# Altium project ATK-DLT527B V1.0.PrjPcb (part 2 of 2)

## Sheet 09_ATK_T527_AUDIO.SchDoc
size A4; Author: ALIENTEK; Revision: 0; Version: V1.0; SheetSize: A4
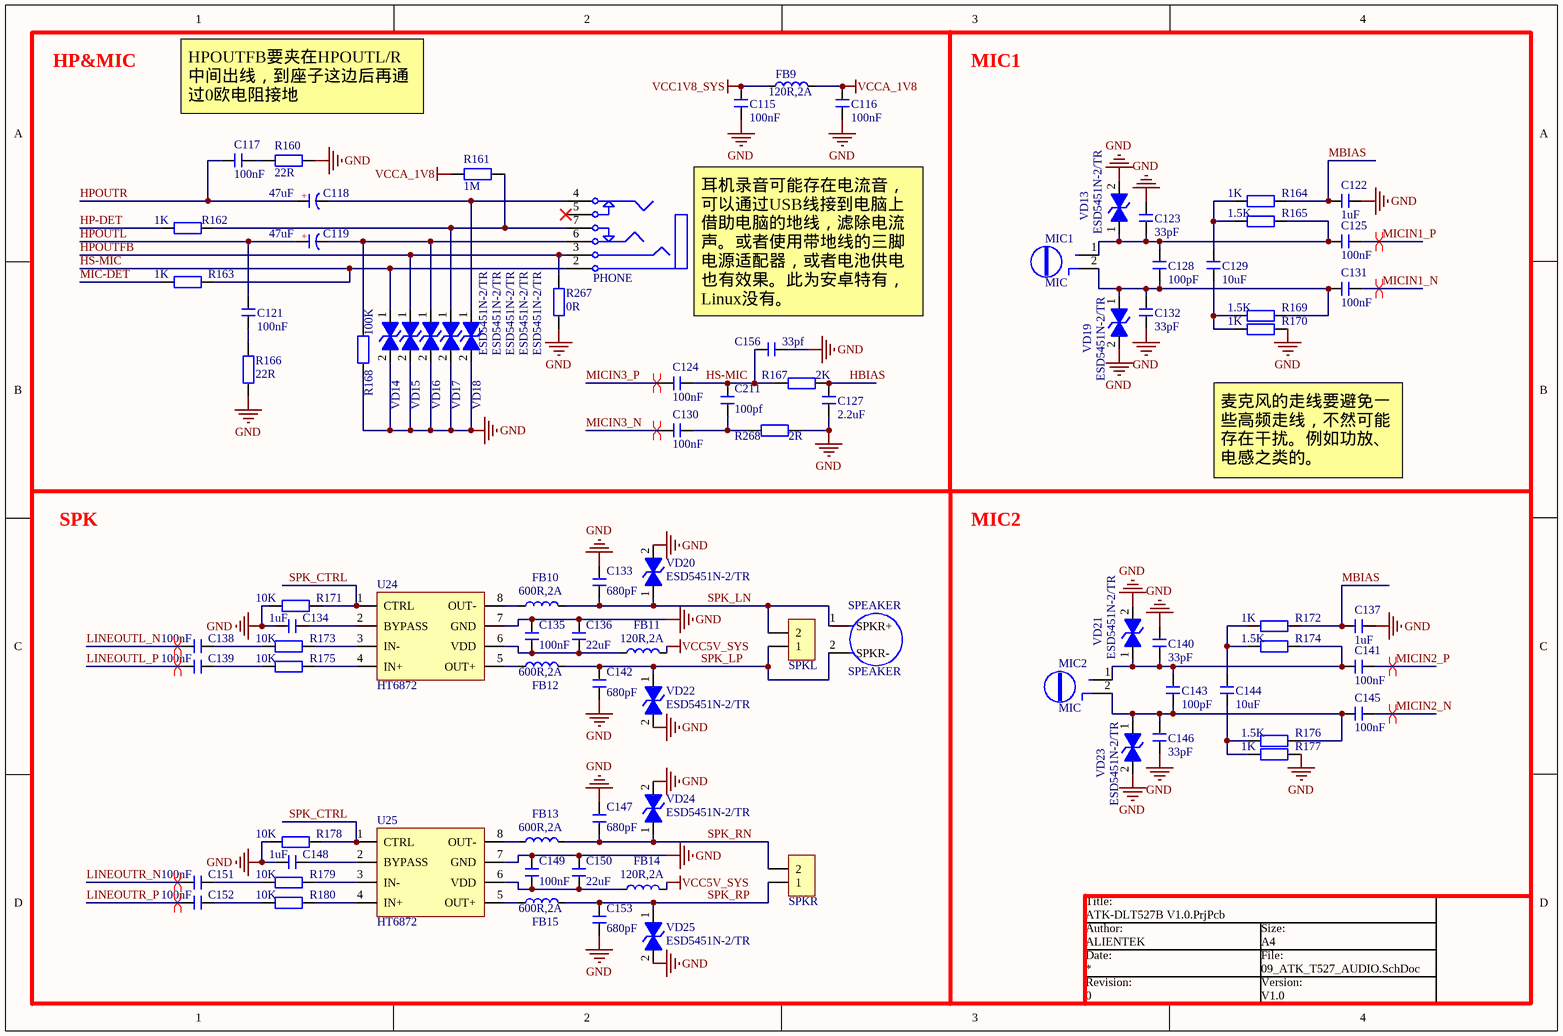
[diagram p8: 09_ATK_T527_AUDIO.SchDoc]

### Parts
C115  100nF  [C 0402]
C116  100nF  [C 0402]
C117  100nF  [C 0402]
C118  47uF  [CM B(4*5.4)]
C119  47uF  [CM B(4*5.4)]
C121  100nF  [C 0402]
C122  1uF  [C 0402]
C123  33pF  [C 0402]
C124  100nF  [C 0402]
C125  100nF  [C 0402]
C127  2.2uF  [C 0402]
C128  100pF  [C 0402]
C129  10uF  [C 0603]
C130  100nF  [C 0402]
C131  100nF  [C 0402]
C132  33pF  [C 0402]
C133  680pF  [C 0402]
C134  1uF  [C 0402]
C135  100nF  [C 0402]
C136  22uF  [C 0603]
C137  1uF  [C 0402]
C138  100nF  [C 0402]
C139  100nF  [C 0402]
C140  33pF  [C 0402]
C141  100nF  [C 0402]
C142  680pF  [C 0402]
C143  100pF  [C 0402]
C144  10uF  [C 0603]
C145  100nF  [C 0402]
C146  33pF  [C 0402]
C147  680pF  [C 0402]
C148  1uF  [C 0402]
C149  100nF  [C 0402]
C150  22uF  [C 0603]
C151  100nF  [C 0402]
C152  100nF  [C 0402]
C153  680pF  [C 0402]
C156  33pf  [C 0402]
C211  100pf  [C 0402]
FB9  120R,2A  [L 0603]
FB10  600R,2A  [L 0603]
FB11  120R,2A  [L 0603]
FB12  600R,2A  [L 0603]
FB13  600R,2A  [L 0603]
FB14  120R,2A  [L 0603]
FB15  600R,2A  [L 0603]
MIC1  MIC  [MIC-6022]
MIC2  MIC  [MIC-6022]
PHONE  PJ342  [PJ342A]  (value not drawn)
R160  22R  [R 0402]
R161  1M  [R 0402]
R162  1K  [R 0402]
R163  1K  [R 0402]
R164  1K  [R 0402]
R165  1.5K  [R 0402]
R166  22R  [R 0402]
R167  2K  [R 0402]
R168  100K  [R 0402]
R169  1.5K  [R 0402]
R170  1K  [R 0402]
R171  10K  [R 0402]
R172  1K  [R 0402]
R173  10K  [R 0402]
R174  1.5K  [R 0402]
R175  10K  [R 0402]
R176  1.5K  [R 0402]
R177  1K  [R 0402]
R178  10K  [R 0402]
R179  10K  [R 0402]
R180  10K  [R 0402]
R267  0R  [R 0402]
R268  2R  [R 0402]
SPEAKER  SPEAKER  [SPEAKER]
SPKL  Header 1X2  [XH2.54-2P H-T]  (value not drawn)
SPKR  Header 1X2  [XH2.54-2P H-T]  (value not drawn)
U24  HT6872  [SOP8_N]
U25  HT6872  [SOP8_N]
VD13  ESD5451N-2/TR  [ESD0402]
VD14  ESD5451N-2/TR  [ESD0402]
VD15  ESD5451N-2/TR  [ESD0402]
VD16  ESD5451N-2/TR  [ESD0402]
VD17  ESD5451N-2/TR  [ESD0402]
VD18  ESD5451N-2/TR  [ESD0402]
VD19  ESD5451N-2/TR  [ESD0402]
VD20  ESD5451N-2/TR  [ESD0402]
VD21  ESD5451N-2/TR  [ESD0402]
VD22  ESD5451N-2/TR  [ESD0402]
VD23  ESD5451N-2/TR  [ESD0402]
VD24  ESD5451N-2/TR  [ESD0402]
VD25  ESD5451N-2/TR  [ESD0402]

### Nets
GND: C115.2 C116.2 C122.1 C123.1 C127.1 C132.2 C133.1 C134.2 C135.1 C136.1 C137.1 C140.1 C142.2 C146.2 C147.1 C148.2 C149.1 C150.1 C153.2 C156.2 R160.2 R166.2 R168.1 R170.1 R171.2 R177.1 R178.2 R267.2 R268.1 U24.7(GND) U25.7(GND) VD13.2 VD14.2 VD15.2 VD16.2 VD17.2 VD18.2 VD19.2 VD20.2 VD21.2 VD22.2 VD23.2 VD24.2 VD25.2
VCC1V8_SYS: C115.1 FB9.1
VCC5V_SYS: FB11.2 FB14.2
VCCA_1V8: C116.1 FB9.2 R161.2
HBIAS: C127.2 R167.1
HP-DET: R162.1
HPOUTFB: PHONE.3 R267.1 VD15.1
HPOUTL: C119.1(A) C121.2
HPOUTR: C117.2 C118.1(A)
HS-MIC: C124.1 C156.1 C211.2 PHONE.2 R163.1 R167.2 VD14.1
LINEOUTL_N: C138.2
LINEOUTL_P: C139.2
LINEOUTR_N: C151.2
LINEOUTR_P: C152.2
MBIAS: C122.2 C137.2 R164.1 R172.1
MIC-DET: R163.2
MICIN1_N: C131.1
MICIN1_P: C125.1
MICIN2_N: C145.1
MICIN2_P: C141.1
MICIN3_N: C130.2
MICIN3_P: C124.2
SPK_CTRL: R171.1 R178.1 U24.1(CTRL) U25.1(CTRL)  [project net PI10]
SPK_LN: C133.2 FB10.2 SPEAKER.1(SPKR+) SPKL.2 VD20.1
SPK_LP: C142.1 FB12.2 SPEAKER.2(SPKR-) SPKL.1 VD22.1
SPK_RN: C147.2 FB13.2 SPKR.2 VD24.1
SPK_RP: C153.1 FB15.2 SPKR.1 VD25.1
NetC117_1: C117.1 R160.1
NetC118_2: C118.2(K) PHONE.4 VD18.1
NetC119_2: C119.2(K) PHONE.6 R168.2 VD16.1
NetC121_1: C121.1 R166.1
NetC123_2: C123.2 C125.2 C128.1 MIC1.1(VCC) R165.1 VD13.1
NetC128_2: C128.2 C131.2 C132.1 MIC1.2(GND) R169.1 VD19.1
NetC129_1: C129.1 R164.2 R165.2
NetC129_2: C129.2 R169.2 R170.2
NetC130_1: C130.1 C211.1 R268.2
NetC134_1: C134.1 U24.2(BYPASS)
NetC135_2: C135.2 C136.2 FB11.1 U24.6(VDD)
NetC138_1: C138.1 R173.2
NetC139_1: C139.1 R175.2
NetC140_2: C140.2 C141.2 C143.1 MIC2.1(VCC) R174.1 VD21.1
NetC143_2: C143.2 C145.2 C146.1 MIC2.2(GND) R176.1 VD23.1
NetC144_1: C144.1 R172.2 R174.2
NetC144_2: C144.2 R176.2 R177.2
NetC148_1: C148.1 U25.2(BYPASS)
NetC149_2: C149.2 C150.2 FB14.1 U25.6(VDD)
NetC151_1: C151.1 R179.2
NetC152_1: C152.1 R180.2
NetFB10_1: FB10.1 U24.8(OUT-)
NetFB12_1: FB12.1 U24.5(OUT+)
NetFB13_1: FB13.1 U25.8(OUT-)
NetFB15_1: FB15.1 U25.5(OUT+)
NetPHONE_7: PHONE.7 R161.1 R162.2 VD17.1
NetR173_1: R173.1 U24.3(IN-)
NetR175_1: R175.1 U24.4(IN+)
NetR179_1: R179.1 U25.3(IN-)
NetR180_1: R180.1 U25.4(IN+)

Not connected (* = marked no-connect by the designer): PHONE 5*

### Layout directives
differential pair: LINEOUTL_N, LINEOUTL_P, LINEOUTR_N, LINEOUTR_P, MICIN1_N, MICIN1_P, MICIN2_N, MICIN2_P, MICIN3_N, MICIN3_P

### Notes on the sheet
- HP&MIC
- HPOUTFB要夹在HPOUTL/R中间出线，到座子这边后再通过0欧电阻接地
- MIC1
- (near C156) 耳机录音可能存在电流音，可以通过USB线接到电脑上借助电脑的地线，滤除电流声。或者使用带地线的三脚电源适配器，或者电池供电也有效果。此为安卓特有，Linux没有。
- 麦克风的走线要避免一些高频走线，不然可能存在干扰。例如功放、电感之类的。
- SPK
- MIC2

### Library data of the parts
C115-C117 C121-C125 C127-C153 C156 C211 = C: 无极性电容; BOM名称: 无极性贴片电容; 版权归属: 正点原子
C118 C119 = C-CM: 贴片电解电容; 版权归属: 源创客
FB9-FB15 = FB: 贴片磁珠; BOM名称: 小功率贴片电感; 版权归属: 正点原子; Parameter: 电感/磁珠
PHONE = Phone-PJ3583: 3.5耳机插座,带检测和麦克风; BOM名称: 耳机插座; 版权归属: 正点原子; Parameter: 接口器件
R160-R180 R267 R268 = R: 电阻; BOM名称: 贴片电阻; 版权归属: 正点原子
SPEAKER = SPEAKER: 喇叭2307
SPKL SPKR = Header 2: 2P接插件; 版权归属: 正点原子; Parameter: 接插件
U24 U25 = HT6872: 功放-4.7W单声道D类功放
VD13-VD25 = ESD5341N: ESD二极管-单向

## Sheet 10_ATK_T527_MIPICSI.SchDoc
size A4; Author: ALIENTEK; Revision: 0; Version: V1.0; SheetSize: A4
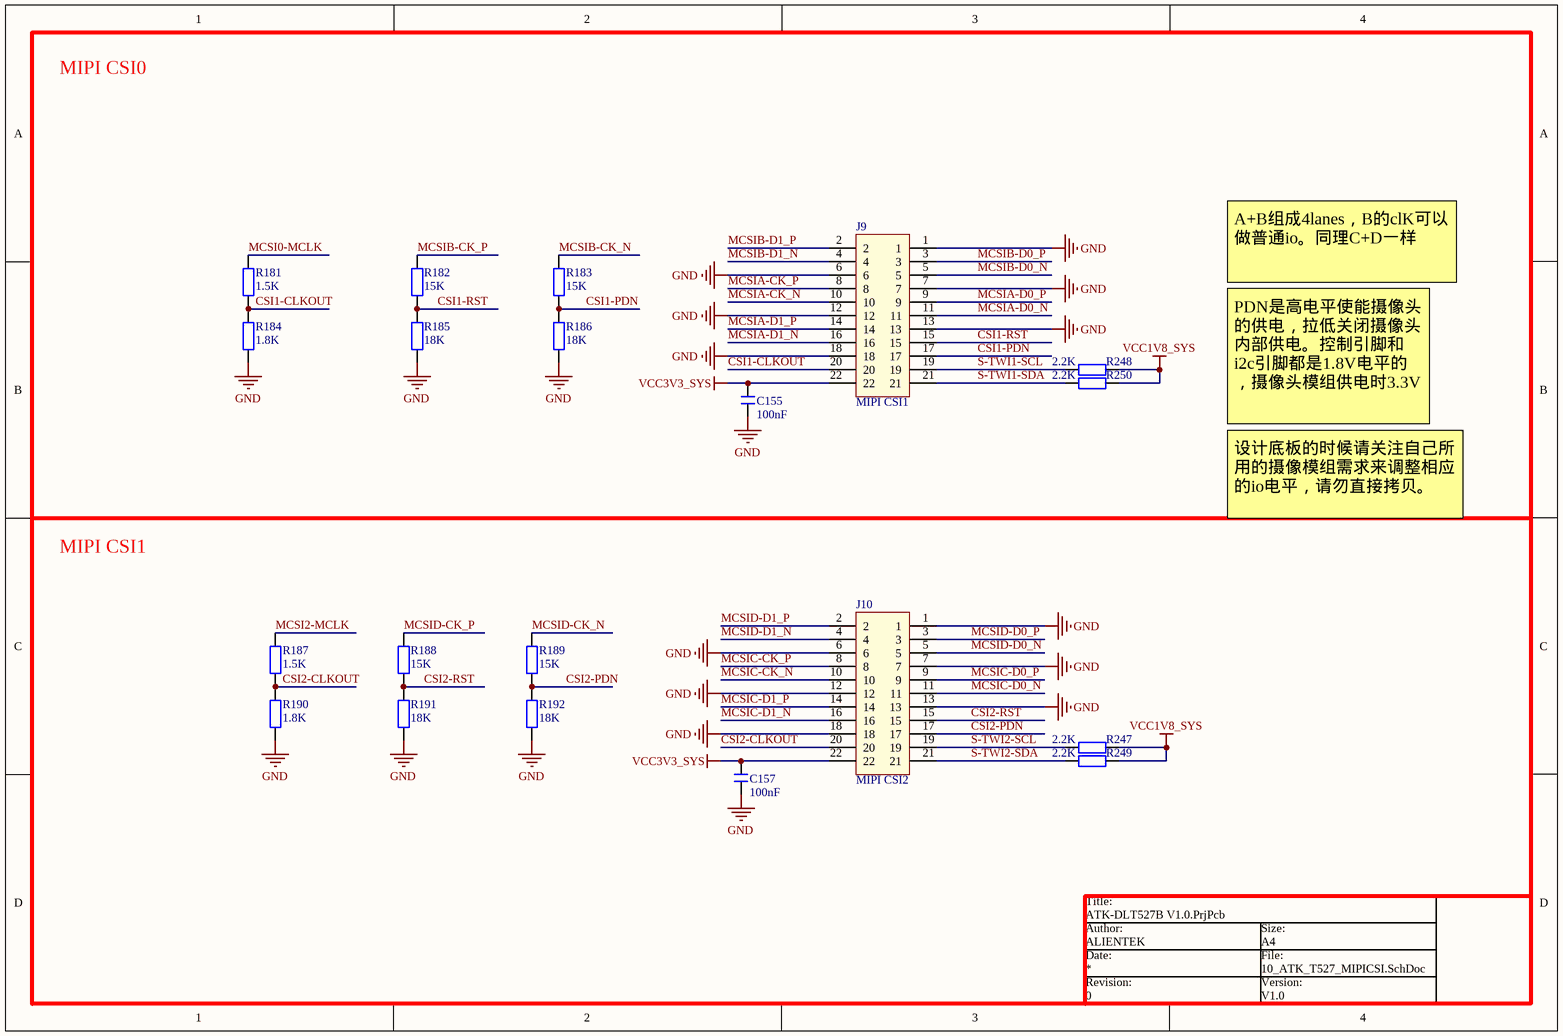
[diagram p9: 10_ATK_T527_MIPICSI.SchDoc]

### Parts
C155  100nF  [C 0402]
C157  100nF  [C 0402]
J9  MIPI CSI1  [HEADER 2.0 2X11P]
J10  MIPI CSI2  [HEADER 2.0 2X11P]
R181  1.5K  [R 0402]
R182  15K  [R 0402]
R183  15K  [R 0402]
R184  1.8K  [R 0402]
R185  18K  [R 0402]
R186  18K  [R 0402]
R187  1.5K  [R 0402]
R188  15K  [R 0402]
R189  15K  [R 0402]
R190  1.8K  [R 0402]
R191  18K  [R 0402]
R192  18K  [R 0402]
R247  2.2K  [R 0402]
R248  2.2K  [R 0402]
R249  2.2K  [R 0402]
R250  2.2K  [R 0402]

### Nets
GND: C155.1 C157.1 J9.1 J9.6 J9.7 J9.12 J9.13 J9.18 J10.1 J10.6 J10.7 J10.12 J10.13 J10.18 R184.1 R185.1 R186.1 R190.1 R191.1 R192.1
VCC1V8_SYS: R247.1 R248.1 R249.1 R250.1
VCC3V3_SYS: C155.2 C157.2 J9.22 J10.22
CSI1-CLKOUT: J9.20 R181.1 R184.2
CSI1-PDN: J9.17 R183.1 R186.2
CSI1-RST: J9.15 R182.1 R185.2
CSI2-CLKOUT: J10.20 R187.1 R190.2
CSI2-PDN: J10.17 R189.1 R192.2
CSI2-RST: J10.15 R188.1 R191.2
MCSI0-MCLK: R181.2
MCSI2-MCLK: R187.2
MCSIA-CK_N: J9.10
MCSIA-CK_P: J9.8
MCSIA-D0_N: J9.11
MCSIA-D0_P: J9.9
MCSIA-D1_N: J9.16
MCSIA-D1_P: J9.14
MCSIB-CK_N: R183.2
MCSIB-CK_P: R182.2
MCSIB-D0_N: J9.5
MCSIB-D0_P: J9.3
MCSIB-D1_N: J9.4
MCSIB-D1_P: J9.2
MCSIC-CK_N: J10.10
MCSIC-CK_P: J10.8
MCSIC-D0_N: J10.11
MCSIC-D0_P: J10.9
MCSIC-D1_N: J10.16
MCSIC-D1_P: J10.14
MCSID-CK_N: R189.2
MCSID-CK_P: R188.2
MCSID-D0_N: J10.5
MCSID-D0_P: J10.3
MCSID-D1_N: J10.4
MCSID-D1_P: J10.2
S-TWI1-SCL: J9.19 R248.2  [project net PM2]
S-TWI1-SDA: J9.21 R250.2  [project net PM3]
S-TWI2-SCL: J10.19 R247.2  [project net PM4]
S-TWI2-SDA: J10.21 R249.2  [project net PM5]

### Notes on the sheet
- MIPI CSI0
- A+B组成4lanes，B的clK可以做普通io。同理C+D一样
- PDN是高电平使能摄像头的供电，拉低关闭摄像头内部供电。控制引脚和i2c引脚都是1.8V电平的，摄像头模组供电时3.3V
- 设计底板的时候请关注自己所用的摄像模组需求来调整相应的io电平，请勿直接拷贝。
- MIPI CSI1

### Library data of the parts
C155 C157 = C: 无极性电容; BOM名称: 无极性贴片电容; 版权归属: 正点原子
J9 J10 = HEADER 2X11P
R181-R192 R247-R250 = R: 电阻; BOM名称: 贴片电阻; 版权归属: 正点原子

## Sheet 11_ATK_T527_CAN485.SchDoc
size A4; Author: ALIENTEK; Revision: 0; Version: V1.0; SheetSize: A4
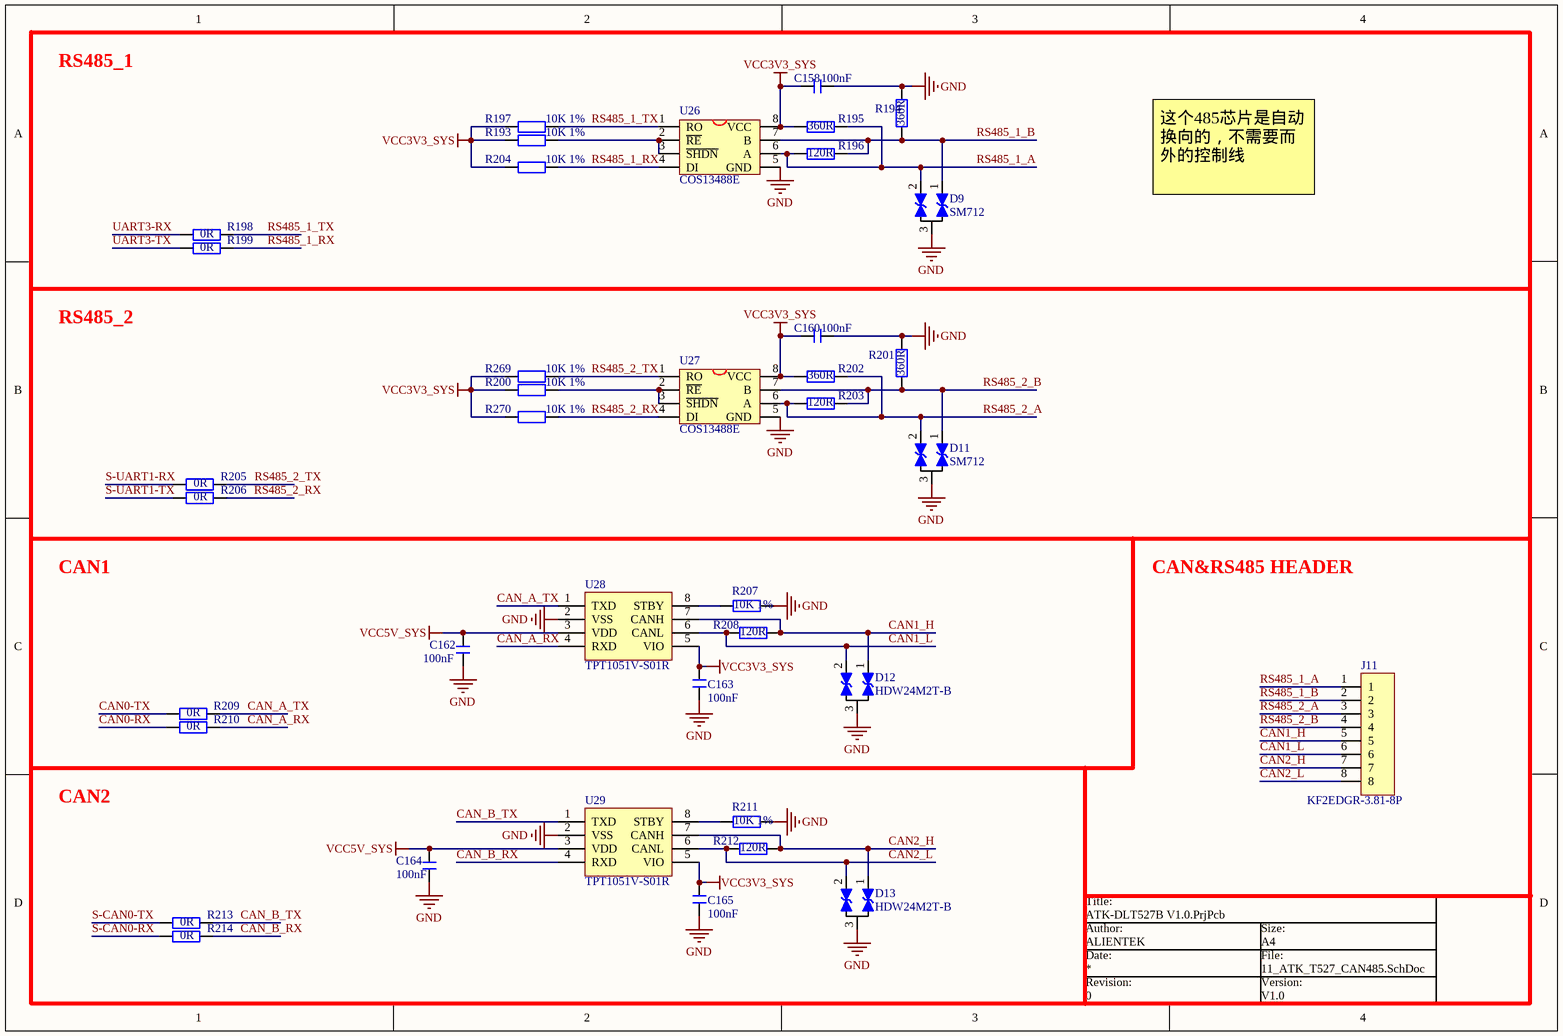
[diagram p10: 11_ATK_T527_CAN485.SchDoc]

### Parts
C158  100nF  [C 0402]
C160  100nF  [C 0402]
C162  100nF  [C 0402]
C163  100nF  [C 0402]
C164  100nF  [C 0402]
C165  100nF  [C 0402]
D9  SM712  [SOT23-3L]
D11  SM712  [SOT23-3L]
D12  HDW24M2T-B  [SOT23-3L]
D13  HDW24M2T-B  [SOT23-3L]
J11  KF2EDGR-3.81-8P  [KF2EDGR_3.81_8P]
R193  10K 1%  [R 0402]
R194  360R  [R 0402]
R195  360R  [R 0402]
R196  120R  [R 0402]
R197  10K 1%  [R 0402]
R198  0R  [R 0402]
R199  0R  [R 0402]
R200  10K 1%  [R 0402]
R201  360R  [R 0402]
R202  360R  [R 0402]
R203  120R  [R 0402]
R204  10K 1%  [R 0402]
R205  0R  [R 0402]
R206  0R  [R 0402]
R207  10K 1%  [R 0402]
R208  120R  [R 0402]
R209  0R  [R 0402]
R210  0R  [R 0402]
R211  10K 1%  [R 0402]
R212  120R  [R 0402]
R213  0R  [R 0402]
R214  0R  [R 0402]
R269  10K 1%  [R 0402]
R270  10K 1%  [R 0402]
U26  COS13488E  [SOP8_N]
U27  COS13488E  [SOP8_N]
U28  TPT1051V-S01R  [SOP8_N]
U29  TPT1051V-S01R  [SOP8_N]

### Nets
GND: C158.2 C160.2 C162.1 C163.2 C164.1 C165.2 D9.3 D11.3 D12.3 D13.3 R194.1 R201.1 R207.2 R211.2 U26.5(GND) U27.5(GND) U28.2(VSS) U29.2(VSS)
VCC3V3_SYS: C158.1 C160.1 C163.1 C165.1 R193.2 R195.2 R197.2 R200.2 R202.2 R204.2 R269.2 R270.2 U26.8(VCC) U27.8(VCC) U28.5(VIO) U29.5(VIO)
VCC5V_SYS: C162.2 C164.2 U28.3(VDD) U29.3(VDD)
CAN0-RX: R210.1
CAN0-TX: R209.1
CAN1_H: D12.1 J11.5 R208.1 U28.7(CANH)
CAN1_L: D12.2 J11.6 R208.2 U28.6(CANL)
CAN2_H: D13.1 J11.7 R212.1 U29.7(CANH)
CAN2_L: D13.2 J11.8 R212.2 U29.6(CANL)
CAN_A_RX: R210.2 U28.4(RXD)
CAN_A_TX: R209.2 U28.1(TXD)
CAN_B_RX: R214.2 U29.4(RXD)
CAN_B_TX: R213.2 U29.1(TXD)
RS485_1_A: D9.2 J11.1 R195.1 R196.2 U26.6(A)
RS485_1_B: D9.1 J11.2 R194.2 R196.1 U26.7(B)
RS485_1_RX: R199.2 R204.1 U26.4(DI)
RS485_1_TX: R197.1 R198.2 U26.1(RO)
RS485_2_A: D11.2 J11.3 R202.1 R203.2 U27.6(A)
RS485_2_B: D11.1 J11.4 R201.2 R203.1 U27.7(B)
RS485_2_RX: R206.2 R270.1 U27.4(DI)
RS485_2_TX: R205.2 R269.1 U27.1(RO)
S-CAN0-RX: R214.1  [project net PL5]
S-CAN0-TX: R213.1  [project net PL4]
S-UART1-RX: R205.1  [project net PL3]
S-UART1-TX: R206.1  [project net PL2]
UART3-RX: R198.1  [project net PI12]
UART3-TX: R199.1  [project net PI11]
NetR193_1: R193.1 U26.2(~{RE}) U26.3(~{SHDN})
NetR200_1: R200.1 U27.2(~{RE}) U27.3(~{SHDN})
NetR207_1: R207.1 U28.8(STBY)
NetR211_1: R211.1 U29.8(STBY)

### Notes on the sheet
- RS485_1
- 这个485芯片是自动换向的，不需要而外的控制线
- RS485_2
- CAN1
- CAN&RS485 HEADER
- CAN2

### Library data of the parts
C158 C160 C162-C165 = C: 无极性贴片电容; 版权归属: 正点原子
D9 D11-D13 = PESD2CAN: ESD
J11 = KF2EDGR-3.81-8P: 接线端子,8脚,间距3.81mm
R193-R197 R200-R204 R207 R208 R211 R212 R269 R270 = R: 贴片电阻; 版权归属: 正点原子
R198 R199 R205 R206 R209 R210 R213 R214 = R: 电阻; BOM名称: 贴片电阻; 版权归属: 正点原子
U28 U29 = MCP2562FDT

## Sheet 12_ATK_T527_DEVICE1.SchDoc
size A3; Date: 13; Author: ALIENTEK; Version: V1.0; SheetSize: A3
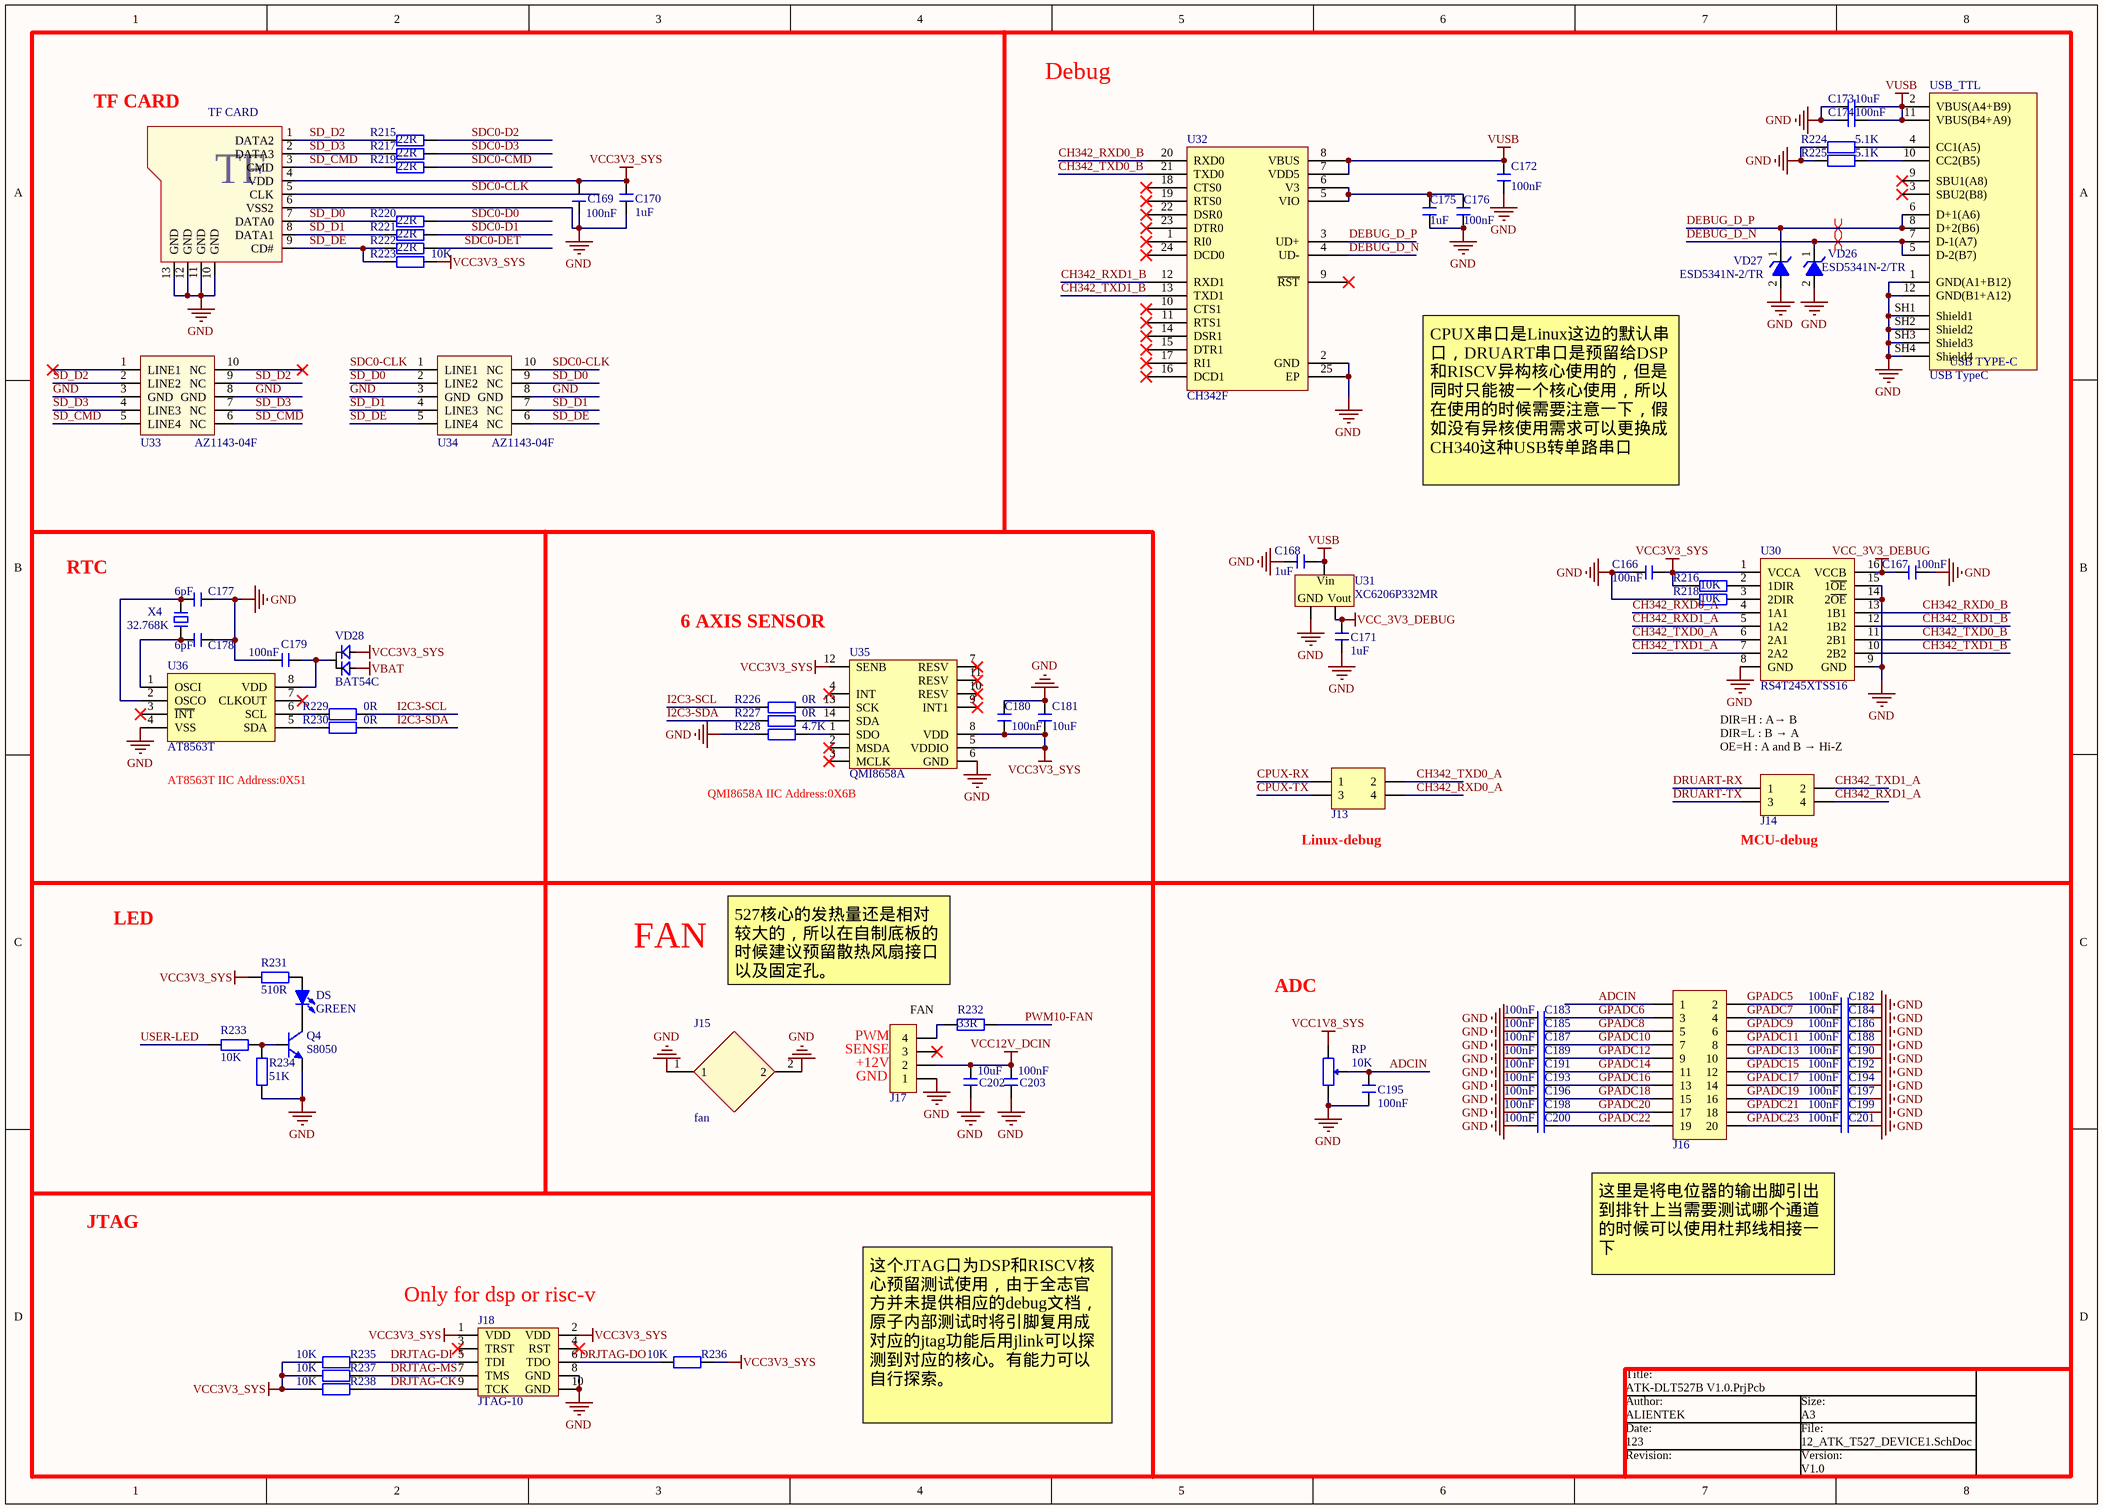
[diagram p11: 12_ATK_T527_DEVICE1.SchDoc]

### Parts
C166  100nF  [C 0402]
C167  100nF  [C 0402]
C168  1uF  [C 0402]
C169  100nF  [C 0402]
C170  1uF  [C 0402]
C171  1uF  [C 0402]
C172  100nF  [C 0402]
C173  10uF  [C 0603]
C174  100nF  [C 0402]
C175  1uF  [C 0402]
C176  100nF  [C 0402]
C177  6pF  [C 0402]
C178  6pF  [C 0402]
C179  100nF  [C 0402]
C180  100nF  [C 0402]
C181  10uF  [C 0603]
C182  100nF  [C 0402]
C183  100nF  [C 0402]
C184  100nF  [C 0402]
C185  100nF  [C 0402]
C186  100nF  [C 0402]
C187  100nF  [C 0402]
C188  100nF  [C 0402]
C189  100nF  [C 0402]
C190  100nF  [C 0402]
C191  100nF  [C 0402]
C192  100nF  [C 0402]
C193  100nF  [C 0402]
C194  100nF  [C 0402]
C195  100nF  [C 0402]
C196  100nF  [C 0402]
C197  100nF  [C 0402]
C198  100nF  [C 0402]
C199  100nF  [C 0402]
C200  100nF  [C 0402]
C201  100nF  [C 0402]
C202  10uF  [C 0603]
C203  100nF  [C 0402]
DS  GREEN  [LED 0805G]
J13  Header2X2  [Header 2.54 2X2P]  (value not drawn)
J14  Header2X2  [Header 2.54 2X2P]  (value not drawn)
J15  fan  [40X40MM_FAN_59MM]
J16  Header 2X10  [Header 2.54 2X10P]  (value not drawn)
J17  Header 1X4  [PH2.0-4P V-T]  (value not drawn)
J18  JTAG-10  [JTAG-10 2.0]
Q4  S8050  [SOT23-3N]
R215  22R  [R 0402]
R216  10K  [R 0402]
R217  22R  [R 0402]
R218  10K  [R 0402]
R219  22R  [R 0402]
R220  22R  [R 0402]
R221  22R  [R 0402]
R222  22R  [R 0402]
R223  10K  [R 0402]
R224  5.1K  [R 0402]
R225  5.1K  [R 0402]
R226  0R  [R 0402]
R227  0R  [R 0402]
R228  4.7K  [R 0402]
R229  0R  [R 0402]
R230  0R  [R 0402]
R231  510R  [R 0402]
R232  33R  [R 0402]
R233  10K  [R 0402]
R234  51K  [R 0402]
R235  10K  [R 0402]
R236  10K  [R 0402]
R237  10K  [R 0402]
R238  10K  [R 0402]
RP  10K  [3362P]
TF_CARD  SD-MICRO-TF  [SD-MICRO-TF]  (value not drawn)
U30  RS4T245XTSS16  [TSSOP16_N]
U31  XC6206P332MR  [SOT23-3L]
U32  CH342F  [VQFN-24_L4.0-W4.0-P0.50-TL-EP2.4]
U33  AZ1143-04F  [DFN2510P10E]
U34  AZ1143-04F  [DFN2510P10E]
U35  QMI8658A  [QFN14]
U36  AT8563T  [SOP8_N]
USB_TTL  USB TypeC  [USB2.0 Type-C]
VD26  ESD5341N-2/TR  [ESD0402]
VD27  ESD5341N-2/TR  [ESD0402]
VD28  BAT54C  [SOT23-3N]
X4  32.768K  [XTAL-2X6H]

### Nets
GND: C166.2 C167.1 C168.1 C169.1 C170.1 C171.1 C172.1 C173.1 C174.1 C175.1 C176.1 C177.1 C178.1 C179.1 C180.1 C181.2 C182.1 C183.1 C184.1 C185.1 C186.1 C187.1 C188.1 C189.1 C190.1 C191.1 C192.1 C193.1 C194.1 C195.2 C196.1 C197.1 C198.1 C199.1 C200.1 C201.1 C202.1 C203.1 J15.1 J15.2 J17.1 J18.8(GND) J18.10(GND) Q4.2(E) R218.1 R224.1 R225.1 R228.2 R234.1 RP.3 TF_CARD.6(VSS2) TF_CARD.10(GND) TF_CARD.11(GND) TF_CARD.12(GND) TF_CARD.13(GND) U30.8(GND) U30.9(GND) U30.14(2~{OE}) U30.15(1~{OE}) U31.1(GND) U32.2(GND) U32.25(EP) U33.3(GND) U33.8(GND) U34.3(GND) U34.8(GND) U35.6(GND) U36.4(VSS) USB_TTL.1(GND(A1+B12)) USB_TTL.12(GND(B1+A12)) USB_TTL.SH1(Shield1) USB_TTL.SH2(Shield2) USB_TTL.SH3(Shield3) USB_TTL.SH4(Shield4) VD26.2 VD27.2
VBAT: VD28.1
VCC1V8_SYS: RP.1
VCC3V3_SYS: C166.1 C169.2 C170.2 C180.2 C181.1 J18.1(VDD) J18.2(VDD) R216.2 R223.2 R231.1 R235.1 R236.2 R237.1 R238.1 TF_CARD.4(VDD) U30.1(VCCA) U35.5(VDDIO) U35.8(VDD) U35.12(SENB) VD28.2
VCC12V_DCIN: C202.2 C203.2 J17.2
VCC_3V3_DEBUG: C167.2 C171.2 U30.16(VCCB) U31.2(Vout)
VUSB: C168.2 C172.2 C173.2 C174.2 U31.3(Vin) U32.7(VDD5) U32.8(VBUS) USB_TTL.2(VBUS(A4+B9)) USB_TTL.11(VBUS(B4+A9))
ADCIN: C195.1 J16.1 RP.2
CH342_RXD0_A: J13.4 U30.4(1A1)
CH342_RXD0_B: U30.13(1B1) U32.20(RXD0)
CH342_RXD1_A: J14.4 U30.5(1A2)
CH342_RXD1_B: U30.12(1B2) U32.12(RXD1)
CH342_TXD0_A: J13.2 U30.6(2A1)
CH342_TXD0_B: U30.11(2B1) U32.21(TXD0)
CH342_TXD1_A: J14.2 U30.7(2A2)
CH342_TXD1_B: U30.10(2B2) U32.13(TXD1)
CPUX-RX: J13.1
CPUX-TX: J13.3
DEBUG_D_N: U32.4(UD-) USB_TTL.5(D-2(B7)) USB_TTL.7(D-1(A7)) VD26.1
DEBUG_D_P: U32.3(UD+) USB_TTL.6(D+1(A6)) USB_TTL.8(D+2(B6)) VD27.1
DRJTAG-CK: J18.9(TCK) R238.2
DRJTAG-DI: J18.5(TDI) R235.2
DRJTAG-DO: J18.6(TDO) R236.1
DRJTAG-MS: J18.7(TMS) R237.2
DRUART-RX: J14.1
DRUART-TX: J14.3
GPADC5: C182.2 J16.2
GPADC6: C183.2 J16.3
GPADC7: C184.2 J16.4
GPADC8: C185.2 J16.5
GPADC9: C186.2 J16.6
GPADC10: C187.2 J16.7
GPADC11: C188.2 J16.8
GPADC12: C189.2 J16.9
GPADC13: C190.2 J16.10
GPADC14: C191.2 J16.11
GPADC15: C192.2 J16.12
GPADC16: C193.2 J16.13
GPADC17: C194.2 J16.14
GPADC18: C196.2 J16.15
GPADC19: C197.2 J16.16
GPADC20: C198.2 J16.17
GPADC21: C199.2 J16.18
GPADC22: C200.2 J16.19
GPADC23: C201.2 J16.20
I2C3-SCL: R226.2 R229.2
I2C3-SDA: R227.2 R230.2
PWM10-FAN: R232.1  [project net PB6]
SD_CMD: R219.1 TF_CARD.3(CMD) U33.5(LINE4) U33.6(NC)
SD_D0: R220.1 TF_CARD.7(DATA0) U34.2(LINE2) U34.9(NC)
SD_D1: R221.1 TF_CARD.8(DATA1) U34.4(LINE3) U34.7(NC)
SD_D2: R215.1 TF_CARD.1(DATA2) U33.2(LINE2) U33.9(NC)
SD_D3: R217.1 TF_CARD.2(DATA3) U33.4(LINE3) U33.7(NC)
SD_DE: R222.1 R223.1 TF_CARD.9(CD#) U34.5(LINE4) U34.6(NC)
SDC0-CLK: TF_CARD.5(CLK) U34.1(LINE1) U34.10(NC)  [project net PF2]
SDC0-CMD: R219.2  [project net PF3]
SDC0-D0: R220.2  [project net PF1]
SDC0-D1: R221.2  [project net PF0]
SDC0-D2: R215.2  [project net PF5]
SDC0-D3: R217.2  [project net PF4]
SDC0-DET: R222.2  [project net PF6]
USER-LED: R233.1  [project net LVDS3-D0_P]
NetC175_2: C175.2 C176.2 U32.5(VIO) U32.6(V3)
NetC177_2: C177.2 U36.2(OSCO) X4.2
NetC178_2: C178.2 U36.1(OSCI) X4.1
NetC179_2: C179.2 U36.8(VDD) VD28.3
NetDS_1: DS.1(A) R231.2
NetDS_2: DS.2(K) Q4.3(C)
NetJ17_4: J17.4 R232.2
NetQ4_1: Q4.1(B) R233.2 R234.2
NetR216_1: R216.1 U30.2(1DIR)
NetR218_2: R218.2 U30.3(2DIR)
NetR224_2: R224.2 USB_TTL.4(CC1(A5))
NetR225_2: R225.2 USB_TTL.10(CC2(B5))
NetR226_1: R226.1 U35.13(SCK)
NetR227_1: R227.1 U35.14(SDA)
NetR228_1: R228.1 U35.1(SDO)
NetR229_1: R229.1 U36.6(SCL)
NetR230_1: R230.1 U36.5(SDA)

Not connected (* = marked no-connect by the designer): J17 3*; J18 3(TRST)* 4(RST)*; U32 1(RI0)* 9(~{RST})* 10(CTS1)* 11(RTS1)* 14(DSR1)* 15(DTR1)* 16(DCD1)* 17(RI1)* 18(CTS0)* 19(RTS0)* 22(DSR0)* 23(DTR0)* 24(DCD0)*; U33 1(LINE1)* 10(NC)*; U35 2(MSDA)* 3(MCLK)* 4(INT)* 7(RESV)* 9(INT1)* 10(RESV)* 11(RESV)*; U36 3(~{INT})* 7(CLKOUT)*; USB_TTL 3(SBU2(B8))* 9(SBU1(A8))*

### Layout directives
differential pair: DEBUG_D_N, DEBUG_D_P

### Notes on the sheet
- (near TF_CARD) TF CARD
- Debug
- CPUX串口是Linux这边的默认串口，DRUART串口是预留给DSP和RISCV异构核心使用的，但是同时只能被一个核心使用，所以在使用的时候需要注意一下，假如没有异核使用需求可以更换成CH340这种USB转单路串口
- RTC
- 6 AXIS SENSOR
- DIR=H : A→ B
- AT8563T IIC Address:0X51
- DIR=L : B → A
- (near J14) OE=H : A and B → Hi-Z
- (near U35) QMI8658A IIC Address:0X6B
- (near J13) Linux-debug
- (near J14) MCU-debug
- LED
- FAN
- 527核心的发热量还是相对较大的，所以在自制底板的时候建议预留散热风扇接口以及固定孔。
- ADC
- (near J17) SENSE
- (near J17) PWM
- (near J17) FAN
- (near J17) GND
- (near J17) +12V
- JTAG
- (near J18) Only for dsp or risc-v
- 这里是将电位器的输出脚引出到排针上当需要测试哪个通道的时候可以使用杜邦线相接一下
- 这个JTAG口为DSP和RISCV核心预留测试使用，由于全志官方并未提供相应的debug文档，原子内部测试时将引脚复用成对应的jtag功能后用jlink可以探测到对应的核心。有能力可以自行探索。

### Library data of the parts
C166-C179 C182-C203 = C: 无极性电容; BOM名称: 无极性贴片电容; 版权归属: 正点原子
C180 C181 = C: 无极性贴片电容; 版权归属: 正点原子
DS = LED-SMD: 贴片LED; 版权归属: 正点原子; Parameter: 发光二极管
J13 J14 = Header 2X2: 2*2P接插件; 版权归属: 正点原子; Parameter: 接插件
J16 = Header 10X2: 10*2P接插件; 版权归属: 正点原子; Parameter: 接插件
J17 = Header 4: 4P接插件; 版权归属: 正点原子; Parameter: 接插件
J18 = IDC JTAG-10: 10Pin JTAG 2.0间距; 版权归属: 正点原子; Parameter: 接口器件
Q4 = 8050-SMD: 高频放大-NPN型; 版权归属: 正点原子; 属性: 40V 1.5A 1W 100MHZ; Parameter: 三极管
R215-R227 R229-R238 = R: 电阻; BOM名称: 贴片电阻; 版权归属: 正点原子
R228 = R: 贴片电阻; 版权归属: 正点原子
RP = RP-SMD: 电位器; BOM名称: 贴片电位器; 版权归属: 正点原子; Parameter: 电阻
TF_CARD = SD-MICRO-TF: SD,MICRO,TF
U30 = RS4T245XTSS16: 4位双电源总线收发器，电压转换，3态缓冲器
U31 = XC6206: LDO 5.5V 200-300mA; 版权归属: 正点原子; Parameter: 芯片
U33 U34 = AZ1143-04F: ESD保护二极管阵列
U35 = SH3001: 6轴传感器
U36 = PCF8563
USB_TTL = USB 2.0 Type C: 12P TypeC 母座; 版权归属: 正点原子; Parameter: 接口器件
VD26 VD27 = ESD5341N: ESD二极管-单向
VD28 = BAT54C: 肖特基二极管（双）
X4 = XTAL-2P: 2脚无源晶振; BOM名称: 2脚晶振; 版权归属: 正点原子

## Sheet 13_ATK_T527_DEVICE2.SchDoc
size A3; Date: 13; Author: ALIENTEK; Revision: 0; Version: V1.0; SheetSize: A3
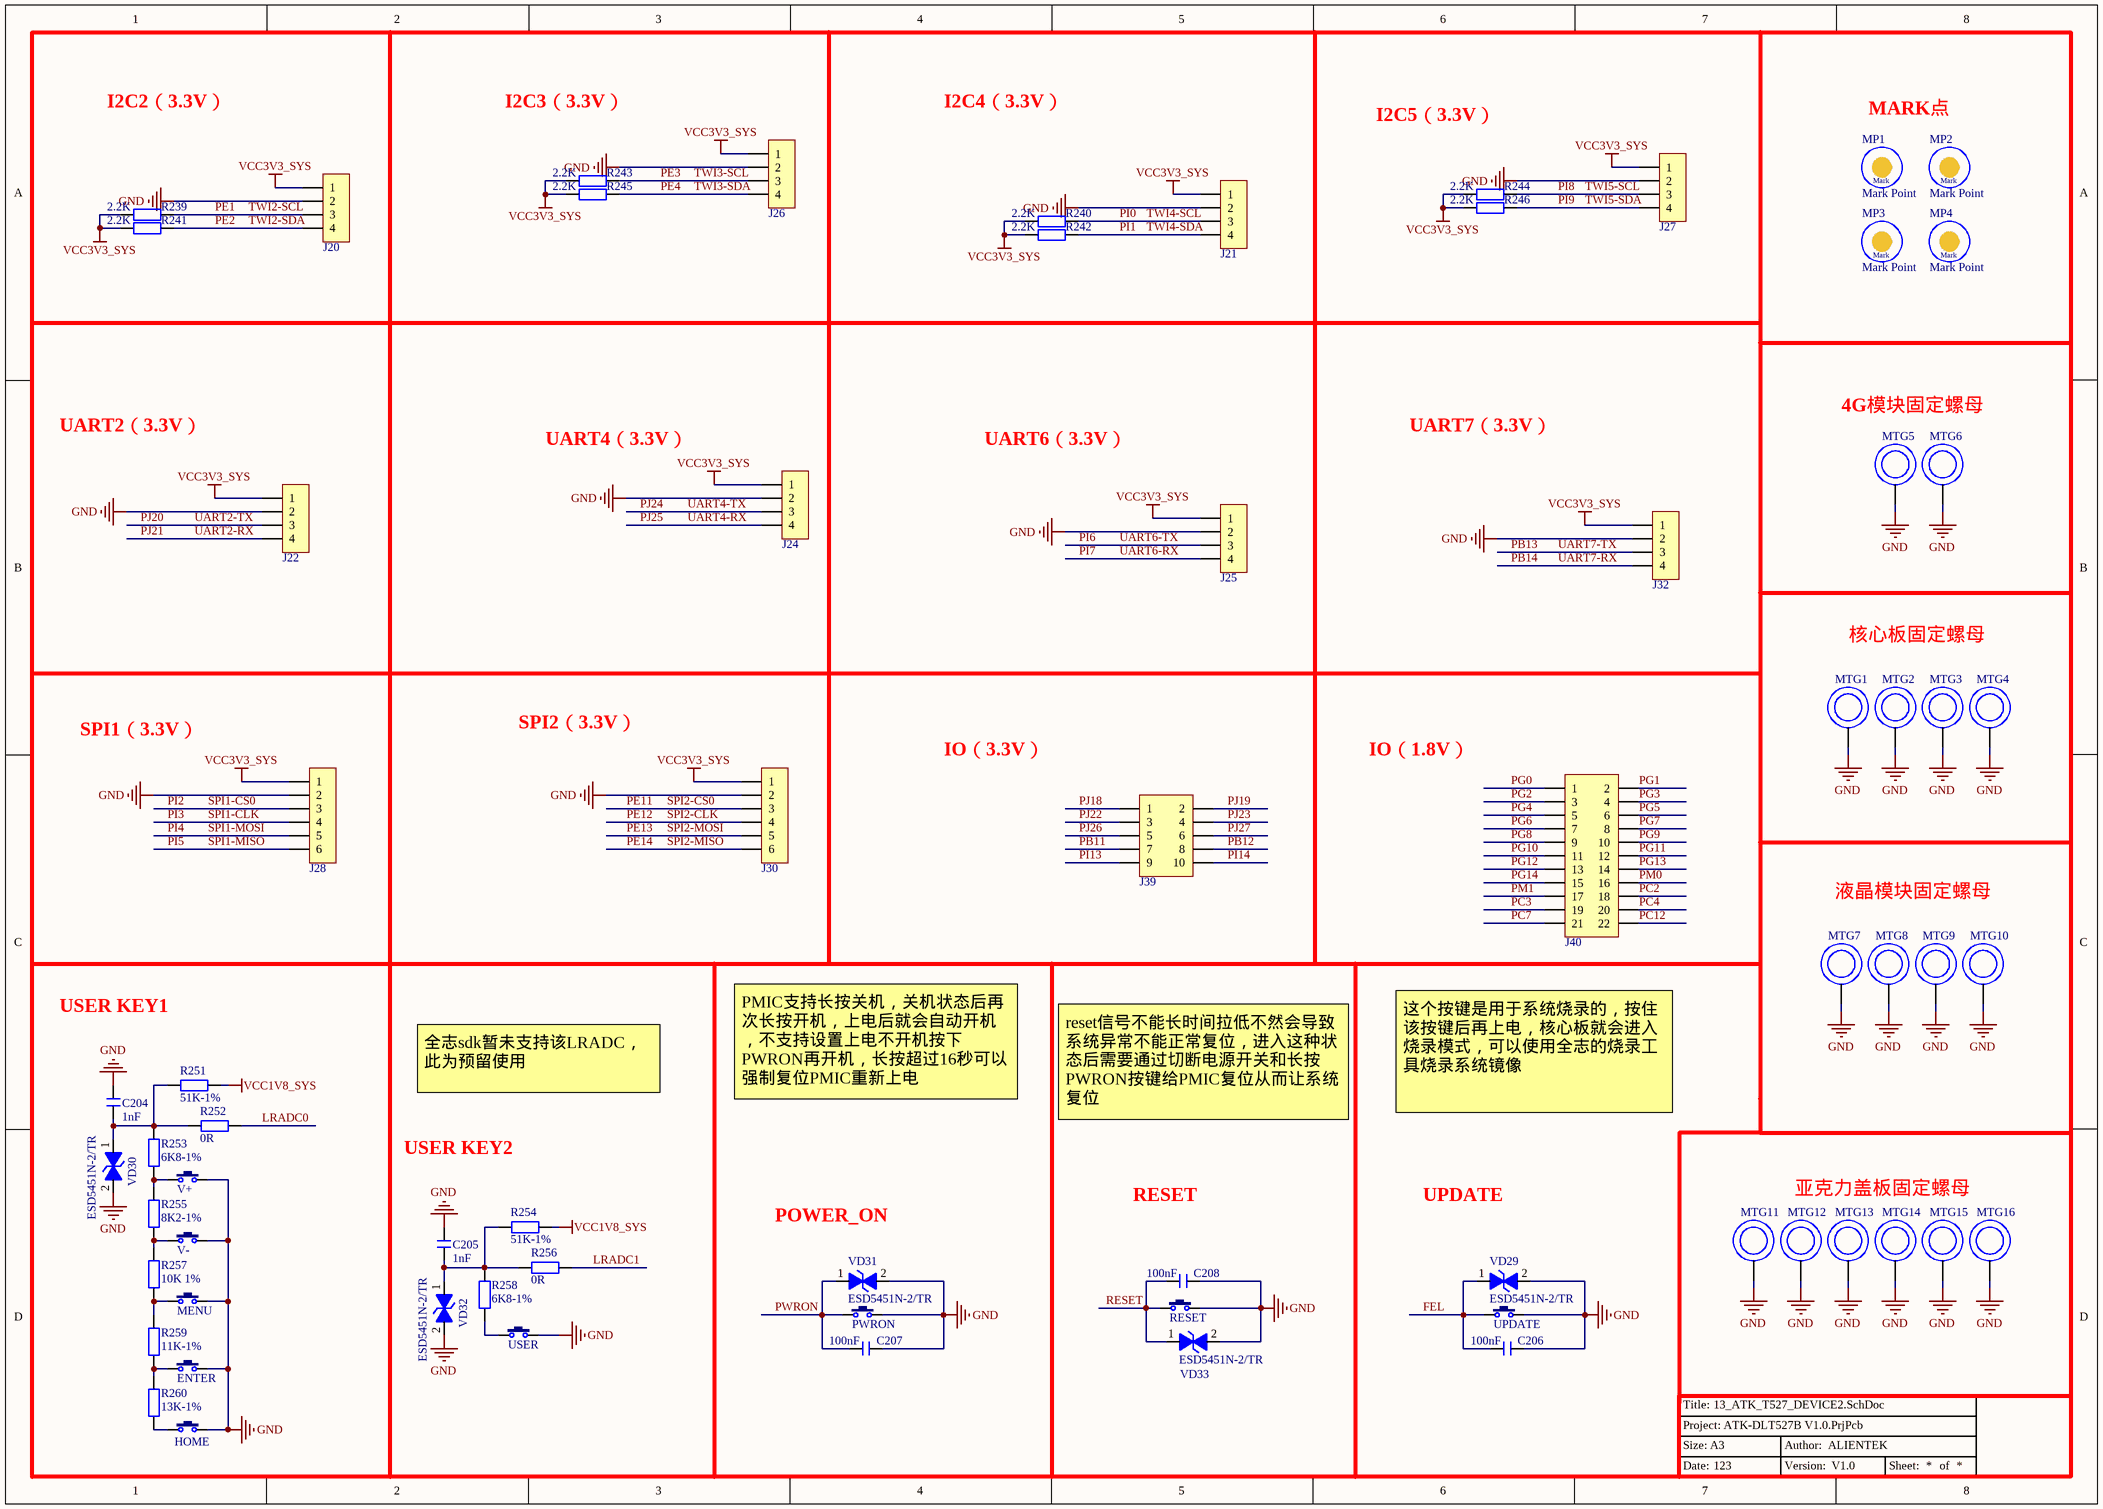
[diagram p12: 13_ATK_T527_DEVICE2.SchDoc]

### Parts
C204  1nF  [C 0402]
C205  1nF  [C 0402]
C206  100nF  [C 0402]
C207  100nF  [C 0402]
C208  100nF  [C 0402]
ENTER  KEY  [KEY 3.2*4.2*2.5 4P SMD]  (value not drawn)
HOME  KEY  [KEY 3.2*4.2*2.5 4P SMD]  (value not drawn)
J20  Header 1X4  [XH2.54-4P V-T]  (value not drawn)
J21  Header 1X4  [XH2.54-4P V-T]  (value not drawn)
J22  Header 1X4  [XH2.54-4P V-T]  (value not drawn)
J24  Header 1X4  [XH2.54-4P V-T]  (value not drawn)
J25  Header 1X4  [XH2.54-4P V-T]  (value not drawn)
J26  Header 1X4  [XH2.54-4P V-T]  (value not drawn)
J27  Header 1X4  [XH2.54-4P V-T]  (value not drawn)
J28  HDR-1X6  [XH2.54-6P V-T]  (value not drawn)
J30  HDR-1X6  [XH2.54-6P V-T]  (value not drawn)
J32  Header 1X4  [XH2.54-4P V-T]  (value not drawn)
J39  Header 5X2  [Header 2.54 2X5P]  (value not drawn)
J40  Header 2X11  [Header 2.54 2X11P]  (value not drawn)
MENU  KEY  [KEY 3.2*4.2*2.5 4P SMD]  (value not drawn)
MP1  Mark Point  [MARK POINT]
MP2  Mark Point  [MARK POINT]
MP3  Mark Point  [MARK POINT]
MP4  Mark Point  [MARK POINT]
MTG1  螺母(M2,贴片螺母柱,铜镀镍,M2x4x1.5+2.9x1.0)  [M2螺丝贴片螺母-直径4mm-高1.5mm]  (value not drawn)
MTG2  螺母(M2,贴片螺母柱,铜镀镍,M2x4x1.5+2.9x1.0)  [M2螺丝贴片螺母-直径4mm-高1.5mm]  (value not drawn)
MTG3  螺母(M2,贴片螺母柱,铜镀镍,M2x4x1.5+2.9x1.0)  [M2螺丝贴片螺母-直径4mm-高1.5mm]  (value not drawn)
MTG4  螺母(M2,贴片螺母柱,铜镀镍,M2x4x1.5+2.9x1.0)  [M2螺丝贴片螺母-直径4mm-高1.5mm]  (value not drawn)
MTG5  螺母(M3*6,贴片螺母柱,白色,SMTSO-M3-6ET)  [铜柱(M2.5,贴片铜柱,黄铜,2.9*2.2+4.0*4.3mm)]  (value not drawn)
MTG6  螺母(M3*6,贴片螺母柱,白色,SMTSO-M3-6ET)  [铜柱(M2.5,贴片铜柱,黄铜,2.9*2.2+4.0*4.3mm)]  (value not drawn)
MTG7  螺母(M3*6,贴片螺母柱,白色,SMTSO-M3-6ET)  [M3*23+6]  (value not drawn)
MTG8  螺母(M3*6,贴片螺母柱,白色,SMTSO-M3-6ET)  [M3*23+6]  (value not drawn)
MTG9  螺母(M3*6,贴片螺母柱,白色,SMTSO-M3-6ET)  [M3*23+6]  (value not drawn)
MTG10  螺母(M3*6,贴片螺母柱,白色,SMTSO-M3-6ET)  [M3*23+6]  (value not drawn)
MTG11  螺母(M3*6,贴片螺母柱,白色,SMTSO-M3-6ET)  [M3-6ET]  (value not drawn)
MTG12  螺母(M3*6,贴片螺母柱,白色,SMTSO-M3-6ET)  [M3-6ET]  (value not drawn)
MTG13  螺母(M3*6,贴片螺母柱,白色,SMTSO-M3-6ET)  [M3-6ET]  (value not drawn)
MTG14  螺母(M3*6,贴片螺母柱,白色,SMTSO-M3-6ET)  [M3-6ET]  (value not drawn)
MTG15  螺母(M3*6,贴片螺母柱,白色,SMTSO-M3-6ET)  [M3-6ET]  (value not drawn)
MTG16  螺母(M3*6,贴片螺母柱,白色,SMTSO-M3-6ET)  [M3-6ET]  (value not drawn)
PWRON  KEY  [KEY 3.2*4.2*2.5 4P SMD]  (value not drawn)
R239  2.2K  [R 0402]
R240  2.2K  [R 0402]
R241  2.2K  [R 0402]
R242  2.2K  [R 0402]
R243  2.2K  [R 0402]
R244  2.2K  [R 0402]
R245  2.2K  [R 0402]
R246  2.2K  [R 0402]
R251  51K-1%  [R 0402]
R252  0R  [R 0402]
R253  6K8-1%  [R 0402]
R254  51K-1%  [R 0402]
R255  8K2-1%  [R 0402]
R256  0R  [R 0402]
R257  10K 1%  [R 0402]
R258  6K8-1%  [R 0402]
R259  11K-1%  [R 0402]
R260  13K-1%  [R 0402]
RESET  KEY  [KEY 3.2*4.2*2.5 4P SMD]  (value not drawn)
UPDATE  KEY  [KEY 3.2*4.2*2.5 4P SMD]  (value not drawn)
USER  KEY  [KEY 3.2*4.2*2.5 4P SMD]  (value not drawn)
V+  KEY  [KEY 3.2*4.2*2.5 4P SMD]  (value not drawn)
V-  KEY  [KEY 3.2*4.2*2.5 4P SMD]  (value not drawn)
VD29  ESD5451N-2/TR  [ESD0402]
VD30  ESD5451N-2/TR  [ESD0402]
VD31  ESD5451N-2/TR  [ESD0402]
VD32  ESD5451N-2/TR  [ESD0402]
VD33  ESD5451N-2/TR  [ESD0402]

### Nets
GND: C204.1 C205.1 C206.2 C207.2 C208.2 ENTER.2 HOME.2 J20.2 J21.2 J22.2 J24.2 J25.2 J26.2 J27.2 J28.2 J30.2 J32.2 MENU.2 MTG1.1 MTG2.1 MTG3.1 MTG4.1 MTG5.0 MTG6.0 MTG7.1 MTG8.1 MTG9.1 MTG10.1 MTG11.1 MTG12.1 MTG13.1 MTG14.1 MTG15.1 MTG16.1 PWRON.2 RESET.2 UPDATE.2 USER.2 V+.2 V-.2 VD29.2 VD30.2 VD31.2 VD32.2 VD33.2
VCC1V8_SYS: R251.2 R254.2
VCC3V3_SYS: J20.1 J21.1 J22.1 J24.1 J25.1 J26.1 J27.1 J28.1 J30.1 J32.1 R239.2 R240.2 R241.2 R242.2 R243.2 R244.2 R245.2 R246.2
FEL: C206.1 UPDATE.1 VD29.1
LRADC0: R252.2
LRADC1: R256.2
PB11: J39.7
PB12: J39.8
PB13: J32.3  [also labelled UART7-TX]
PB14: J32.4  [also labelled UART7-RX]
PC2: J40.18
PC3: J40.19
PC4: J40.20
PC7: J40.21
PC12: J40.22
PE1: J20.3 R239.1  [also labelled TWI2-SCL]
PE2: J20.4 R241.1  [also labelled TWI2-SDA]
PE3: J26.3 R243.1  [also labelled TWI3-SCL]
PE4: J26.4 R245.1  [also labelled TWI3-SDA]
PE11: J30.3  [also labelled SPI2-CS0]
PE12: J30.4  [also labelled SPI2-CLK]
PE13: J30.5  [also labelled SPI2-MOSI]
PE14: J30.6  [also labelled SPI2-MISO]
PG0: J40.1
PG1: J40.2
PG2: J40.3
PG3: J40.4
PG4: J40.5
PG5: J40.6
PG6: J40.7
PG7: J40.8
PG8: J40.9
PG9: J40.10
PG10: J40.11  [project net I2S1-MCLK]
PG11: J40.12  [project net I2S1-BCLK]
PG12: J40.13  [project net I2S1-LRCK]
PG13: J40.14  [project net I2S1-DIN1]
PG14: J40.15  [project net I2S1-DOUT1]
PI0: J21.3 R240.1  [also labelled TWI4-SCL]
PI1: J21.4 R242.1  [also labelled TWI4-SDA]
PI2: J28.3  [also labelled SPI1-CS0]
PI3: J28.4  [also labelled SPI1-CLK]
PI4: J28.5  [also labelled SPI1-MOSI]
PI5: J28.6  [also labelled SPI1-MISO]
PI6: J25.3  [also labelled UART6-TX]
PI7: J25.4  [also labelled UART6-RX]
PI8: J27.3 R244.1  [also labelled TWI5-SCL]
PI9: J27.4 R246.1  [also labelled TWI5-SDA]
PI13: J39.9
PI14: J39.10
PJ18: J39.1  [project net LVDS3-D3_P]
PJ19: J39.2  [project net 4G-RST]
PJ20: J22.3  [also labelled UART2-TX]  [project net LCD1-DATA20]
PJ21: J22.4  [also labelled UART2-RX]  [project net LCD1-DATA21]
PJ22: J39.3  [project net LCD1-DATA22]
PJ23: J39.4  [project net LCD1-DATA23]
PJ24: J24.3  [also labelled UART4-TX]  [project net LCD1-CLK]
PJ25: J24.4  [also labelled UART4-RX]  [project net LCD1-DE]
PJ26: J39.5  [project net LCD1-HSYNC]
PJ27: J39.6  [project net LCD1-VSYNC]
PM0: J40.16
PM1: J40.17
PWRON: C207.1 PWRON.1 VD31.1
RESET: C208.1 RESET.1 VD33.1
NetC204_2: C204.2 R251.1 R252.1 R253.2 VD30.1
NetC205_2: C205.2 R254.1 R256.1 R258.2 VD32.1
NetENTER_1: ENTER.1 R259.1 R260.2
NetHOME_1: HOME.1 R260.1
NetMENU_1: MENU.1 R257.1 R259.2
NetR253_1: R253.1 R255.2 V+.1
NetR255_1: R255.1 R257.2 V-.1
NetR258_1: R258.1 USER.1

Not connected (* = marked no-connect by the designer): MP1 1; MP2 1; MP3 1; MP4 1

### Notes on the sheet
- I2C2（3.3V）
- I2C3（3.3V）
- I2C4（3.3V）
- I2C5（3.3V）
- MARK点
- UART2（3.3V）
- UART4（3.3V）
- UART6（3.3V）
- UART7（3.3V）
- 4G模块固定螺母
- 核心板固定螺母
- SPI1（3.3V）
- SPI2（3.3V）
- IO（3.3V）
- IO（1.8V）
- 液晶模块固定螺母
- USER KEY1
- 全志sdk暂未支持该LRADC，此为预留使用
- PMIC支持长按关机，关机状态后再次长按开机，上电后就会自动开机，不支持设置上电不开机按下PWRON再开机，长按超过16秒可以强制复位PMIC重新上电
- reset信号不能长时间拉低不然会导致系统异常不能正常复位，进入这种状态后需要通过切断电源开关和长按PWRON按键给PMIC复位从而让系统复位
- 这个按键是用于系统烧录的，按住该按键后再上电，核心板就会进入烧录模式，可以使用全志的烧录工具烧录系统镜像
- USER KEY2
- POWER_ON
- RESET
- UPDATE
- 亚克力盖板固定螺母

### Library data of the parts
C204-C208 = C: 无极性电容; BOM名称: 无极性贴片电容; 版权归属: 正点原子
ENTER HOME MENU PWRON RESET UPDATE USER V+ V- = KEY: 按键; BOM名称: 3x6轻触开关; 版权归属: 正点原子; Parameter: 按键/开关
J20-J22 J24-J27 J32 = Header 4: 4P接插件; 版权归属: 正点原子; Parameter: 接插件
J28 J30 = Header 6: 6P接插件; 版权归属: 正点原子; Parameter: 接插件
J39 = Header 5X2: 5*2P接插件; 版权归属: 正点原子; Parameter: 接插件
J40 = Header 11X2: 11*2P接插件; 版权归属: 正点原子; Parameter: 接插件
MP1-MP4 = MARK
MTG1-MTG4 = MTG_Hole: 301020006
MTG5-MTG16 = MTG_Hole: 301020001
R239-R246 R251-R260 = R: 电阻; BOM名称: 贴片电阻; 版权归属: 正点原子
VD29-VD33 = ESD5341N: ESD二极管-单向

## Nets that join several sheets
EXT_EN: 02_ATK_T527_CORE (U38.C35), 03_ATK_T527_POWER (R8.1 R15.1)
GND: 02_ATK_T527_CORE (44 pins), 03_ATK_T527_POWER (43 pins), 04_ATK_T527_NET1 (34 pins), 05_ATK_T527_NET2 (34 pins), 06_ATK_T527_DISPLAY (40 pins), 07_ATK_T527_HDMI&DP (44 pins), 08_ATK_T527_USBOTG&HOST (90 pins), 09_ATK_T527_AUDIO (44 pins), 10_ATK_T527_MIPICSI (20 pins), 11_ATK_T527_CAN485 (18 pins), 12_ATK_T527_DEVICE1 (76 pins), 13_ATK_T527_DEVICE2 (45 pins)
VBAT: 03_ATK_T527_POWER (BAT1.1 C21.1), 12_ATK_T527_DEVICE1 (VD28.1)
VCC1V8_SYS: 03_ATK_T527_POWER (5 pins), 09_ATK_T527_AUDIO (C115.1 FB9.1), 10_ATK_T527_MIPICSI (R247.1 R248.1 R249.1 R250.1), 12_ATK_T527_DEVICE1 (RP.1), 13_ATK_T527_DEVICE2 (R251.2 R254.2)
VCC3V3_SYS: 03_ATK_T527_POWER (10 pins), 04_ATK_T527_NET1 (FB1.2 FB2.2), 05_ATK_T527_NET2 (FB4.2 FB5.2), 06_ATK_T527_DISPLAY (12 pins), 07_ATK_T527_HDMI&DP (D6.1 R140.1 R146.1), 08_ATK_T527_USBOTG&HOST (6 pins), 10_ATK_T527_MIPICSI (C155.2 C157.2 J9.22 J10.22), 11_ATK_T527_CAN485 (16 pins), 12_ATK_T527_DEVICE1 (20 pins), 13_ATK_T527_DEVICE2 (18 pins)
VCC5V_SYS: 03_ATK_T527_POWER (13 pins), 06_ATK_T527_DISPLAY (15 pins), 07_ATK_T527_HDMI&DP (D5.1), 08_ATK_T527_USBOTG&HOST (8 pins), 09_ATK_T527_AUDIO (FB11.2 FB14.2), 11_ATK_T527_CAN485 (C162.2 C164.2 U28.3 U29.3)
VCC12V_DCIN: 03_ATK_T527_POWER (19 pins), 12_ATK_T527_DEVICE1 (C202.2 C203.2 J17.2)
VCC-CORE: 02_ATK_T527_CORE (8 pins), 03_ATK_T527_POWER (D1.2 R263.2)
4G-RST: 02_ATK_T527_CORE (U38.A20), 08_ATK_T527_USBOTG&HOST (R266.2), 13_ATK_T527_DEVICE2 (J39.2)
CAN0-RX: 02_ATK_T527_CORE (U38.C66), 11_ATK_T527_CAN485 (R210.1)
CAN0-TX: 02_ATK_T527_CORE (U38.C65), 11_ATK_T527_CAN485 (R209.1)
CPUX-RX: 02_ATK_T527_CORE (U38.D5), 12_ATK_T527_DEVICE1 (J13.1)
CPUX-TX: 02_ATK_T527_CORE (U38.D6), 12_ATK_T527_DEVICE1 (J13.3)
CT1_INT: 02_ATK_T527_CORE (U38.A69), 06_ATK_T527_DISPLAY (5 pins)
CT1_RST: 02_ATK_T527_CORE (U38.A70), 06_ATK_T527_DISPLAY (LVDS1.28 MIPI_DSI1.6 R131.2 RGBLCD.35)
CT1_SCL: 02_ATK_T527_CORE (U38.D39), 06_ATK_T527_DISPLAY (LVDS1.34 MIPI_DSI1.4 R121.2 RGBLCD.38)
CT1_SDA: 02_ATK_T527_CORE (U38.D40), 06_ATK_T527_DISPLAY (LVDS1.33 MIPI_DSI1.5 R123.2 RGBLCD.36)
CT2_INT: 02_ATK_T527_CORE (U38.A71), 06_ATK_T527_DISPLAY (C59.1 MIPI_DSI2.3 R128.2)
CT2_RST: 02_ATK_T527_CORE (U38.A72), 06_ATK_T527_DISPLAY (MIPI_DSI2.6 R130.2)
CT2_SCL: 02_ATK_T527_CORE (U38.D9), 06_ATK_T527_DISPLAY (MIPI_DSI2.4 R120.2)
CT2_SDA: 02_ATK_T527_CORE (U38.D8), 06_ATK_T527_DISPLAY (MIPI_DSI2.5 R122.2)
DRJTAG-CK: 02_ATK_T527_CORE (U38.C75), 12_ATK_T527_DEVICE1 (J18.9 R238.2)
DRJTAG-DI: 02_ATK_T527_CORE (U38.C77), 12_ATK_T527_DEVICE1 (J18.5 R235.2)
DRJTAG-DO: 02_ATK_T527_CORE (U38.C76), 12_ATK_T527_DEVICE1 (J18.6 R236.1)
DRJTAG-MS: 02_ATK_T527_CORE (U38.C74), 12_ATK_T527_DEVICE1 (J18.7 R237.2)
DRUART-RX: 02_ATK_T527_CORE (U38.C79), 12_ATK_T527_DEVICE1 (J14.1)
DRUART-TX: 02_ATK_T527_CORE (U38.C78), 12_ATK_T527_DEVICE1 (J14.3)
EDP-AUX_N: 02_ATK_T527_CORE (U38.D43), 07_ATK_T527_HDMI&DP (C82.1)
EDP-AUX_P: 02_ATK_T527_CORE (U38.D44), 07_ATK_T527_HDMI&DP (C81.1)
EDP-HPD: 02_ATK_T527_CORE (U38.D41), 07_ATK_T527_HDMI&DP (R147.1)
EDP-TX0_N: 02_ATK_T527_CORE (U38.D55), 07_ATK_T527_HDMI&DP (C74.1)
EDP-TX0_P: 02_ATK_T527_CORE (U38.D56), 07_ATK_T527_HDMI&DP (C73.1)
EDP-TX1_N: 02_ATK_T527_CORE (U38.D52), 07_ATK_T527_HDMI&DP (C76.1)
EDP-TX1_P: 02_ATK_T527_CORE (U38.D53), 07_ATK_T527_HDMI&DP (C75.1)
EDP-TX2_N: 02_ATK_T527_CORE (U38.D49), 07_ATK_T527_HDMI&DP (C78.1)
EDP-TX2_P: 02_ATK_T527_CORE (U38.D50), 07_ATK_T527_HDMI&DP (C77.1)
EDP-TX3_N: 02_ATK_T527_CORE (U38.D46), 07_ATK_T527_HDMI&DP (C80.1)
EDP-TX3_P: 02_ATK_T527_CORE (U38.D47), 07_ATK_T527_HDMI&DP (C79.1)
FEL: 02_ATK_T527_CORE (U38.C47), 13_ATK_T527_DEVICE2 (C206.1 UPDATE.1 VD29.1)
GPADC3: 02_ATK_T527_CORE (U38.A31), 06_ATK_T527_DISPLAY (MIPI_DSI1.8)
GPADC4: 02_ATK_T527_CORE (U38.A32), 06_ATK_T527_DISPLAY (MIPI_DSI2.8)
GPADC5: 02_ATK_T527_CORE (U38.A33), 12_ATK_T527_DEVICE1 (C182.2 J16.2)
GPADC6: 02_ATK_T527_CORE (U38.A34), 12_ATK_T527_DEVICE1 (C183.2 J16.3)
GPADC7: 02_ATK_T527_CORE (U38.A35), 12_ATK_T527_DEVICE1 (C184.2 J16.4)
GPADC8: 02_ATK_T527_CORE (U38.A36), 12_ATK_T527_DEVICE1 (C185.2 J16.5)
GPADC9: 02_ATK_T527_CORE (U38.A37), 12_ATK_T527_DEVICE1 (C186.2 J16.6)
GPADC10: 02_ATK_T527_CORE (U38.A38), 12_ATK_T527_DEVICE1 (C187.2 J16.7)
GPADC11: 02_ATK_T527_CORE (U38.A39), 12_ATK_T527_DEVICE1 (C188.2 J16.8)
GPADC12: 02_ATK_T527_CORE (U38.A40), 12_ATK_T527_DEVICE1 (C189.2 J16.9)
GPADC13: 02_ATK_T527_CORE (U38.C1), 12_ATK_T527_DEVICE1 (C190.2 J16.10)
GPADC14: 02_ATK_T527_CORE (U38.C2), 12_ATK_T527_DEVICE1 (C191.2 J16.11)
GPADC15: 02_ATK_T527_CORE (U38.C3), 12_ATK_T527_DEVICE1 (C192.2 J16.12)
GPADC16: 02_ATK_T527_CORE (U38.C4), 12_ATK_T527_DEVICE1 (C193.2 J16.13)
GPADC17: 02_ATK_T527_CORE (U38.C5), 12_ATK_T527_DEVICE1 (C194.2 J16.14)
GPADC18: 02_ATK_T527_CORE (U38.C6), 12_ATK_T527_DEVICE1 (C196.2 J16.15)
GPADC19: 02_ATK_T527_CORE (U38.C7), 12_ATK_T527_DEVICE1 (C197.2 J16.16)
GPADC20: 02_ATK_T527_CORE (U38.C8), 12_ATK_T527_DEVICE1 (C198.2 J16.17)
GPADC21: 02_ATK_T527_CORE (U38.C9), 12_ATK_T527_DEVICE1 (C199.2 J16.18)
GPADC22: 02_ATK_T527_CORE (U38.C10), 12_ATK_T527_DEVICE1 (C200.2 J16.19)
GPADC23: 02_ATK_T527_CORE (U38.C11), 12_ATK_T527_DEVICE1 (C201.2 J16.20)
HBIAS: 02_ATK_T527_CORE (U38.C13), 09_ATK_T527_AUDIO (C127.2 R167.1)
HCEC: 02_ATK_T527_CORE (U38.D61), 07_ATK_T527_HDMI&DP (R142.1)
HHPD: 02_ATK_T527_CORE (U38.D58), 07_ATK_T527_HDMI&DP (C71.2 R141.1)
HP-DET: 02_ATK_T527_CORE (U38.C15), 09_ATK_T527_AUDIO (R162.1)
HPOUTFB: 02_ATK_T527_CORE (U38.C32), 09_ATK_T527_AUDIO (PHONE.3 R267.1 VD15.1)
HPOUTL: 02_ATK_T527_CORE (U38.C31), 09_ATK_T527_AUDIO (C119.1 C121.2)
HPOUTR: 02_ATK_T527_CORE (U38.C33), 09_ATK_T527_AUDIO (C117.2 C118.1)
HSCL: 02_ATK_T527_CORE (U38.D60), 07_ATK_T527_HDMI&DP (R138.1)
HSDA: 02_ATK_T527_CORE (U38.D59), 07_ATK_T527_HDMI&DP (R139.1)
HTX0_N: 02_ATK_T527_CORE (U38.D66), 07_ATK_T527_HDMI&DP (HDMI.9 U12.2 U12.9)
HTX0_P: 02_ATK_T527_CORE (U38.D67), 07_ATK_T527_HDMI&DP (HDMI.7 U12.1 U12.10)
HTX1_N: 02_ATK_T527_CORE (U38.D69), 07_ATK_T527_HDMI&DP (HDMI.6 U11.5 U11.6)
HTX1_P: 02_ATK_T527_CORE (U38.D70), 07_ATK_T527_HDMI&DP (HDMI.4 U11.4 U11.7)
HTX2_N: 02_ATK_T527_CORE (U38.D72), 07_ATK_T527_HDMI&DP (HDMI.3 U11.2 U11.9)
HTX2_P: 02_ATK_T527_CORE (U38.D73), 07_ATK_T527_HDMI&DP (HDMI.1 U11.1 U11.10)
HTXC_N: 02_ATK_T527_CORE (U38.D63), 07_ATK_T527_HDMI&DP (HDMI.12 U12.5 U12.6)
HTXC_P: 02_ATK_T527_CORE (U38.D64), 07_ATK_T527_HDMI&DP (HDMI.10 U12.4 U12.7)
I2S1-BCLK: 02_ATK_T527_CORE (U38.A51), 13_ATK_T527_DEVICE2 (J40.12)
I2S1-DIN1: 02_ATK_T527_CORE (U38.A49), 13_ATK_T527_DEVICE2 (J40.14)
I2S1-DOUT1: 02_ATK_T527_CORE (U38.A48), 13_ATK_T527_DEVICE2 (J40.15)
I2S1-LRCK: 02_ATK_T527_CORE (U38.A50), 13_ATK_T527_DEVICE2 (J40.13)
I2S1-MCLK: 02_ATK_T527_CORE (U38.A52), 13_ATK_T527_DEVICE2 (J40.11)
LCD0-CLK: 02_ATK_T527_CORE (U38.D35), 06_ATK_T527_DISPLAY (R116.1 RGBLCD.30)
LCD0-DATA0: 02_ATK_T527_CORE (U38.D15), 06_ATK_T527_DISPLAY (RGBLCD.21)
LCD0-DATA1: 02_ATK_T527_CORE (U38.D14), 06_ATK_T527_DISPLAY (RGBLCD.22)
LCD0-DATA2: 02_ATK_T527_CORE (U38.D17), 06_ATK_T527_DISPLAY (R80.1 RGBLCD.23)
LCD0-DATA3: 02_ATK_T527_CORE (U38.D18), 06_ATK_T527_DISPLAY (R82.1 RGBLCD.24)
LCD0-DATA4: 02_ATK_T527_CORE (U38.D19), 06_ATK_T527_DISPLAY (R84.1 RGBLCD.25)
LCD0-DATA5: 02_ATK_T527_CORE (U38.D20), 06_ATK_T527_DISPLAY (R86.1 RGBLCD.26)
LCD0-DATA6: 02_ATK_T527_CORE (U38.D21), 06_ATK_T527_DISPLAY (R88.1 RGBLCD.27)
LCD0-DATA7: 02_ATK_T527_CORE (U38.D22), 06_ATK_T527_DISPLAY (R90.1 RGBLCD.28)
LCD0-DATA8: 02_ATK_T527_CORE (U38.D13), 06_ATK_T527_DISPLAY (RGBLCD.12)
LCD0-DATA9: 02_ATK_T527_CORE (U38.D12), 06_ATK_T527_DISPLAY (RGBLCD.13)
LCD0-DATA10: 02_ATK_T527_CORE (U38.D23), 06_ATK_T527_DISPLAY (R92.1 RGBLCD.14)
LCD0-DATA11: 02_ATK_T527_CORE (U38.D24), 06_ATK_T527_DISPLAY (R94.1 RGBLCD.15)
LCD0-DATA12: 02_ATK_T527_CORE (U38.D25), 06_ATK_T527_DISPLAY (R96.1 RGBLCD.16)
LCD0-DATA13: 02_ATK_T527_CORE (U38.D26), 06_ATK_T527_DISPLAY (R98.1 RGBLCD.17)
LCD0-DATA14: 02_ATK_T527_CORE (U38.D27), 06_ATK_T527_DISPLAY (R100.1 RGBLCD.18)
LCD0-DATA15: 02_ATK_T527_CORE (U38.D28), 06_ATK_T527_DISPLAY (R102.1 RGBLCD.19)
LCD0-DATA16: 02_ATK_T527_CORE (U38.D11), 06_ATK_T527_DISPLAY (RGBLCD.3)
LCD0-DATA17: 02_ATK_T527_CORE (U38.D10), 06_ATK_T527_DISPLAY (RGBLCD.4)
LCD0-DATA18: 02_ATK_T527_CORE (U38.D29), 06_ATK_T527_DISPLAY (R104.1 RGBLCD.5)
LCD0-DATA19: 02_ATK_T527_CORE (U38.D30), 06_ATK_T527_DISPLAY (R106.1 RGBLCD.6)
LCD0-DATA20: 02_ATK_T527_CORE (U38.D31), 06_ATK_T527_DISPLAY (R108.1 RGBLCD.7)
LCD0-DATA21: 02_ATK_T527_CORE (U38.D32), 06_ATK_T527_DISPLAY (R110.1 RGBLCD.8)
LCD0-DATA22: 02_ATK_T527_CORE (U38.D33), 06_ATK_T527_DISPLAY (R112.1 RGBLCD.9)
LCD0-DATA23: 02_ATK_T527_CORE (U38.D34), 06_ATK_T527_DISPLAY (R114.1 RGBLCD.10)
LCD0-DE: 02_ATK_T527_CORE (U38.D36), 06_ATK_T527_DISPLAY (R118.1 RGBLCD.33)
LCD0-HSYNC: 02_ATK_T527_CORE (U38.D37), 06_ATK_T527_DISPLAY (RGBLCD.31)
LCD0-VSYNC: 02_ATK_T527_CORE (U38.D38), 06_ATK_T527_DISPLAY (RGBLCD.32)
LCD1-BL: 02_ATK_T527_CORE (U38.C72), 06_ATK_T527_DISPLAY (LVDS1.27 MIPI_DSI1.7 R125.2 RGBLCD.34)
LCD1-CLK: 02_ATK_T527_CORE (U38.A25), 13_ATK_T527_DEVICE2 (J24.3)
LCD1-DATA20: 02_ATK_T527_CORE (U38.A21), 13_ATK_T527_DEVICE2 (J22.3)
LCD1-DATA21: 02_ATK_T527_CORE (U38.A22), 13_ATK_T527_DEVICE2 (J22.4)
LCD1-DATA22: 02_ATK_T527_CORE (U38.A23), 13_ATK_T527_DEVICE2 (J39.3)
LCD1-DATA23: 02_ATK_T527_CORE (U38.A24), 13_ATK_T527_DEVICE2 (J39.4)
LCD1-DE: 02_ATK_T527_CORE (U38.A26), 13_ATK_T527_DEVICE2 (J24.4)
LCD1-HSYNC: 02_ATK_T527_CORE (U38.A27), 13_ATK_T527_DEVICE2 (J39.5)
LCD1-RST: 02_ATK_T527_CORE (U38.A73), 06_ATK_T527_DISPLAY (R127.2 R133.2 RGBLCD.40)
LCD1-VSYNC: 02_ATK_T527_CORE (U38.A28), 13_ATK_T527_DEVICE2 (J39.6)
LCD2-BL: 02_ATK_T527_CORE (U38.C73), 06_ATK_T527_DISPLAY (MIPI_DSI2.7 R124.2)
LCD2-RST: 02_ATK_T527_CORE (U38.A74), 06_ATK_T527_DISPLAY (R126.2 R132.2)
LINEOUTL_N: 02_ATK_T527_CORE (U38.C27), 09_ATK_T527_AUDIO (C138.2)
LINEOUTL_P: 02_ATK_T527_CORE (U38.C26), 09_ATK_T527_AUDIO (C139.2)
LINEOUTR_N: 02_ATK_T527_CORE (U38.C29), 09_ATK_T527_AUDIO (C151.2)
LINEOUTR_P: 02_ATK_T527_CORE (U38.C28), 09_ATK_T527_AUDIO (C152.2)
LRADC0: 02_ATK_T527_CORE (U38.A29), 13_ATK_T527_DEVICE2 (R252.2)
LRADC1: 02_ATK_T527_CORE (U38.A30), 13_ATK_T527_DEVICE2 (R256.2)
LVDS2-CK_N: 02_ATK_T527_CORE (U38.A8), 05_ATK_T527_NET2 (R68.1)
LVDS2-CK_P: 02_ATK_T527_CORE (U38.A7), 05_ATK_T527_NET2 (R69.1)
LVDS2-D0_N: 02_ATK_T527_CORE (U38.A2), 05_ATK_T527_NET2 (R58.1)
LVDS2-D0_P: 02_ATK_T527_CORE (U38.A1), 05_ATK_T527_NET2 (R59.1)
LVDS2-D1_N: 02_ATK_T527_CORE (U38.A4), 05_ATK_T527_NET2 (R79.1)
LVDS2-D1_P: 02_ATK_T527_CORE (U38.A3), 05_ATK_T527_NET2 (R63.1)
LVDS2-D2_N: 02_ATK_T527_CORE (U38.A6), 05_ATK_T527_NET2 (R64.1)
LVDS2-D2_P: 02_ATK_T527_CORE (U38.A5), 05_ATK_T527_NET2 (R65.1)
LVDS2-D3_N: 02_ATK_T527_CORE (U38.A10), 05_ATK_T527_NET2 (R75.1)
LVDS2-D3_P: 02_ATK_T527_CORE (U38.A9), 05_ATK_T527_NET2 (R76.1)
LVDS3-CK_N: 02_ATK_T527_CORE (U38.A18), 05_ATK_T527_NET2 (C57.1 U10.12)
LVDS3-CK_P: 02_ATK_T527_CORE (U38.A17), 05_ATK_T527_NET2 (R77.1)
LVDS3-D0_N: 02_ATK_T527_CORE (U38.A12), 05_ATK_T527_NET2 (R61.1)
LVDS3-D0_P: 02_ATK_T527_CORE (U38.A11), 12_ATK_T527_DEVICE1 (R233.1)
LVDS3-D1_N: 02_ATK_T527_CORE (U38.A14), 05_ATK_T527_NET2 (R62.1)
LVDS3-D1_P: 02_ATK_T527_CORE (U38.A13), 05_ATK_T527_NET2 (R60.1)
LVDS3-D2_N: 02_ATK_T527_CORE (U38.A16), 05_ATK_T527_NET2 (R66.1)
LVDS3-D2_P: 02_ATK_T527_CORE (U38.A15), 05_ATK_T527_NET2 (R67.1)
LVDS3-D3_P: 02_ATK_T527_CORE (U38.A19), 08_ATK_T527_USBOTG&HOST (R265.2), 13_ATK_T527_DEVICE2 (J39.1)
MBIAS: 02_ATK_T527_CORE (U38.C12), 09_ATK_T527_AUDIO (C122.2 C137.2 R164.1 R172.1)
MCSI0-MCLK: 02_ATK_T527_CORE (U38.A64), 10_ATK_T527_MIPICSI (R181.2)
MCSI2-MCLK: 02_ATK_T527_CORE (U38.A79), 10_ATK_T527_MIPICSI (R187.2)
MCSIA-CK_N: 02_ATK_T527_CORE (U38.B57), 10_ATK_T527_MIPICSI (J9.10)
MCSIA-CK_P: 02_ATK_T527_CORE (U38.B58), 10_ATK_T527_MIPICSI (J9.8)
MCSIA-D0_N: 02_ATK_T527_CORE (U38.B53), 10_ATK_T527_MIPICSI (J9.11)
MCSIA-D0_P: 02_ATK_T527_CORE (U38.B54), 10_ATK_T527_MIPICSI (J9.9)
MCSIA-D1_N: 02_ATK_T527_CORE (U38.B55), 10_ATK_T527_MIPICSI (J9.16)
MCSIA-D1_P: 02_ATK_T527_CORE (U38.B56), 10_ATK_T527_MIPICSI (J9.14)
MCSIB-CK_N: 02_ATK_T527_CORE (U38.B64), 10_ATK_T527_MIPICSI (R183.2)
MCSIB-CK_P: 02_ATK_T527_CORE (U38.B65), 10_ATK_T527_MIPICSI (R182.2)
MCSIB-D0_N: 02_ATK_T527_CORE (U38.B60), 10_ATK_T527_MIPICSI (J9.5)
MCSIB-D0_P: 02_ATK_T527_CORE (U38.B61), 10_ATK_T527_MIPICSI (J9.3)
MCSIB-D1_N: 02_ATK_T527_CORE (U38.B62), 10_ATK_T527_MIPICSI (J9.4)
MCSIB-D1_P: 02_ATK_T527_CORE (U38.B63), 10_ATK_T527_MIPICSI (J9.2)
MCSIC-CK_N: 02_ATK_T527_CORE (U38.B71), 10_ATK_T527_MIPICSI (J10.10)
MCSIC-CK_P: 02_ATK_T527_CORE (U38.B72), 10_ATK_T527_MIPICSI (J10.8)
MCSIC-D0_N: 02_ATK_T527_CORE (U38.B67), 10_ATK_T527_MIPICSI (J10.11)
MCSIC-D0_P: 02_ATK_T527_CORE (U38.B68), 10_ATK_T527_MIPICSI (J10.9)
MCSIC-D1_N: 02_ATK_T527_CORE (U38.B69), 10_ATK_T527_MIPICSI (J10.16)
MCSIC-D1_P: 02_ATK_T527_CORE (U38.B70), 10_ATK_T527_MIPICSI (J10.14)
MCSID-CK_N: 02_ATK_T527_CORE (U38.B78), 10_ATK_T527_MIPICSI (R189.2)
MCSID-CK_P: 02_ATK_T527_CORE (U38.B79), 10_ATK_T527_MIPICSI (R188.2)
MCSID-D0_N: 02_ATK_T527_CORE (U38.B74), 10_ATK_T527_MIPICSI (J10.5)
MCSID-D0_P: 02_ATK_T527_CORE (U38.B75), 10_ATK_T527_MIPICSI (J10.3)
MCSID-D1_N: 02_ATK_T527_CORE (U38.B76), 10_ATK_T527_MIPICSI (J10.4)
MCSID-D1_P: 02_ATK_T527_CORE (U38.B77), 10_ATK_T527_MIPICSI (J10.2)
MIC-DET: 02_ATK_T527_CORE (U38.C14), 09_ATK_T527_AUDIO (R163.2)
MICIN1_N: 02_ATK_T527_CORE (U38.C17), 09_ATK_T527_AUDIO (C131.1)
MICIN1_P: 02_ATK_T527_CORE (U38.C18), 09_ATK_T527_AUDIO (C125.1)
MICIN2_N: 02_ATK_T527_CORE (U38.C20), 09_ATK_T527_AUDIO (C145.1)
MICIN2_P: 02_ATK_T527_CORE (U38.C21), 09_ATK_T527_AUDIO (C141.1)
MICIN3_N: 02_ATK_T527_CORE (U38.C23), 09_ATK_T527_AUDIO (C130.2)
MICIN3_P: 02_ATK_T527_CORE (U38.C24), 09_ATK_T527_AUDIO (C124.2)
PB6: 02_ATK_T527_CORE (U38.D7), 12_ATK_T527_DEVICE1 (R232.1)
PB11: 02_ATK_T527_CORE (U38.D4), 13_ATK_T527_DEVICE2 (J39.7)
PB12: 02_ATK_T527_CORE (U38.D3), 13_ATK_T527_DEVICE2 (J39.8)
PB13: 02_ATK_T527_CORE (U38.D2), 13_ATK_T527_DEVICE2 (J32.3)
PB14: 02_ATK_T527_CORE (U38.D1), 13_ATK_T527_DEVICE2 (J32.4)
PC2: 02_ATK_T527_CORE (U38.B32), 13_ATK_T527_DEVICE2 (J40.18)
PC3: 02_ATK_T527_CORE (U38.B31), 13_ATK_T527_DEVICE2 (J40.19)
PC4: 02_ATK_T527_CORE (U38.B30), 13_ATK_T527_DEVICE2 (J40.20)
PC7: 02_ATK_T527_CORE (U38.B29), 13_ATK_T527_DEVICE2 (J40.21)
PC12: 02_ATK_T527_CORE (U38.B28), 13_ATK_T527_DEVICE2 (J40.22)
PE1: 02_ATK_T527_CORE (U38.A65), 13_ATK_T527_DEVICE2 (J20.3 R239.1)
PE2: 02_ATK_T527_CORE (U38.A66), 13_ATK_T527_DEVICE2 (J20.4 R241.1)
PE3: 02_ATK_T527_CORE (U38.A67), 13_ATK_T527_DEVICE2 (J26.3 R243.1)
PE4: 02_ATK_T527_CORE (U38.A68), 13_ATK_T527_DEVICE2 (J26.4 R245.1)
PE11: 02_ATK_T527_CORE (U38.A75), 13_ATK_T527_DEVICE2 (J30.3)
PE12: 02_ATK_T527_CORE (U38.A76), 13_ATK_T527_DEVICE2 (J30.4)
PE13: 02_ATK_T527_CORE (U38.A77), 13_ATK_T527_DEVICE2 (J30.5)
PE14: 02_ATK_T527_CORE (U38.A78), 13_ATK_T527_DEVICE2 (J30.6)
PF0: 02_ATK_T527_CORE (U38.B34), 12_ATK_T527_DEVICE1 (R221.2)
PF1: 02_ATK_T527_CORE (U38.B35), 12_ATK_T527_DEVICE1 (R220.2)
PF2: 02_ATK_T527_CORE (U38.B36), 12_ATK_T527_DEVICE1 (TF_CARD.5 U34.1 U34.10)
PF3: 02_ATK_T527_CORE (U38.B37), 12_ATK_T527_DEVICE1 (R219.2)
PF4: 02_ATK_T527_CORE (U38.B38), 12_ATK_T527_DEVICE1 (R217.2)
PF5: 02_ATK_T527_CORE (U38.B39), 12_ATK_T527_DEVICE1 (R215.2)
PF6: 02_ATK_T527_CORE (U38.B33), 12_ATK_T527_DEVICE1 (R222.2)
PG0: 02_ATK_T527_CORE (U38.A62), 13_ATK_T527_DEVICE2 (J40.1)
PG1: 02_ATK_T527_CORE (U38.A61), 13_ATK_T527_DEVICE2 (J40.2)
PG2: 02_ATK_T527_CORE (U38.A60), 13_ATK_T527_DEVICE2 (J40.3)
PG3: 02_ATK_T527_CORE (U38.A59), 13_ATK_T527_DEVICE2 (J40.4)
PG4: 02_ATK_T527_CORE (U38.A58), 13_ATK_T527_DEVICE2 (J40.5)
PG5: 02_ATK_T527_CORE (U38.A57), 13_ATK_T527_DEVICE2 (J40.6)
PG6: 02_ATK_T527_CORE (U38.A56), 13_ATK_T527_DEVICE2 (J40.7)
PG7: 02_ATK_T527_CORE (U38.A55), 13_ATK_T527_DEVICE2 (J40.8)
PG8: 02_ATK_T527_CORE (U38.A54), 13_ATK_T527_DEVICE2 (J40.9)
PG9: 02_ATK_T527_CORE (U38.A53), 13_ATK_T527_DEVICE2 (J40.10)
PH0: 02_ATK_T527_CORE (U38.B14), 04_ATK_T527_NET1 (R32.1)
PH1: 02_ATK_T527_CORE (U38.B15), 04_ATK_T527_NET1 (R31.1)
PH2: 02_ATK_T527_CORE (U38.B16), 04_ATK_T527_NET1 (R36.1)
PH3: 02_ATK_T527_CORE (U38.B21), 04_ATK_T527_NET1 (R46.1)
PH4: 02_ATK_T527_CORE (U38.B7), 04_ATK_T527_NET1 (U7.17)
PH5: 02_ATK_T527_CORE (U38.B8), 04_ATK_T527_NET1 (U7.18)
PH6: 02_ATK_T527_CORE (U38.B10), 04_ATK_T527_NET1 (U7.20)
PH7: 02_ATK_T527_CORE (U38.B9), 04_ATK_T527_NET1 (U7.19)
PH8: 02_ATK_T527_CORE (U38.B19), 04_ATK_T527_NET1 (R44.1)
PH9: 02_ATK_T527_CORE (U38.B2), 04_ATK_T527_NET1 (R43.1)
PH10: 02_ATK_T527_CORE (U38.B3), 04_ATK_T527_NET1 (R42.1)
PH11: 02_ATK_T527_CORE (U38.B25), 08_ATK_T527_USBOTG&HOST (D7.1)
PH12: 02_ATK_T527_CORE (U38.B26), 08_ATK_T527_USBOTG&HOST (R149.1 U16.4)
PH13: 02_ATK_T527_CORE (U38.B23), 04_ATK_T527_NET1 (C41.1 U7.12)
PH14: 02_ATK_T527_CORE (U38.B12), 04_ATK_T527_NET1 (R34.1)
PH15: 02_ATK_T527_CORE (U38.B13), 04_ATK_T527_NET1 (R33.1)
PH16: 02_ATK_T527_CORE (U38.B17), 04_ATK_T527_NET1 (R35.1)
PH17: 02_ATK_T527_CORE (U38.B5), 04_ATK_T527_NET1 (U7.15)
PH18: 02_ATK_T527_CORE (U38.B6), 04_ATK_T527_NET1 (U7.16)
PH19: 02_ATK_T527_CORE (U38.B27), 08_ATK_T527_USBOTG&HOST (R264.1)
PI0: 02_ATK_T527_CORE (U38.C50), 13_ATK_T527_DEVICE2 (J21.3 R240.1)
PI1: 02_ATK_T527_CORE (U38.C51), 13_ATK_T527_DEVICE2 (J21.4 R242.1)
PI2: 02_ATK_T527_CORE (U38.C52), 13_ATK_T527_DEVICE2 (J28.3)
PI3: 02_ATK_T527_CORE (U38.C53), 13_ATK_T527_DEVICE2 (J28.4)
PI4: 02_ATK_T527_CORE (U38.C54), 13_ATK_T527_DEVICE2 (J28.5)
PI5: 02_ATK_T527_CORE (U38.C55), 13_ATK_T527_DEVICE2 (J28.6)
PI6: 02_ATK_T527_CORE (U38.C56), 13_ATK_T527_DEVICE2 (J25.3)
PI7: 02_ATK_T527_CORE (U38.C57), 13_ATK_T527_DEVICE2 (J25.4)
PI8: 02_ATK_T527_CORE (U38.C58), 13_ATK_T527_DEVICE2 (J27.3 R244.1)
PI9: 02_ATK_T527_CORE (U38.C59), 13_ATK_T527_DEVICE2 (J27.4 R246.1)
PI10: 02_ATK_T527_CORE (U38.C60), 09_ATK_T527_AUDIO (R171.1 R178.1 U24.1 U25.1)
PI11: 02_ATK_T527_CORE (U38.C61), 11_ATK_T527_CAN485 (R199.1)
PI12: 02_ATK_T527_CORE (U38.C62), 11_ATK_T527_CAN485 (R198.1)
PI13: 02_ATK_T527_CORE (U38.C63), 13_ATK_T527_DEVICE2 (J39.9)
PI14: 02_ATK_T527_CORE (U38.C64), 13_ATK_T527_DEVICE2 (J39.10)
PL2: 02_ATK_T527_CORE (U38.C68), 11_ATK_T527_CAN485 (R206.1)
PL3: 02_ATK_T527_CORE (U38.C69), 11_ATK_T527_CAN485 (R205.1)
PL4: 02_ATK_T527_CORE (U38.C70), 11_ATK_T527_CAN485 (R213.1)
PL5: 02_ATK_T527_CORE (U38.C71), 11_ATK_T527_CAN485 (R214.1)
PM0: 02_ATK_T527_CORE (U38.A47), 13_ATK_T527_DEVICE2 (J40.16)
PM1: 02_ATK_T527_CORE (U38.A46), 13_ATK_T527_DEVICE2 (J40.17)
PM2: 02_ATK_T527_CORE (U38.A45), 10_ATK_T527_MIPICSI (J9.19 R248.2)
PM3: 02_ATK_T527_CORE (U38.A44), 10_ATK_T527_MIPICSI (J9.21 R250.2)
PM4: 02_ATK_T527_CORE (U38.A43), 10_ATK_T527_MIPICSI (J10.19 R247.2)
PM5: 02_ATK_T527_CORE (U38.A42), 10_ATK_T527_MIPICSI (J10.21 R249.2)
PWRON: 02_ATK_T527_CORE (U38.C46), 13_ATK_T527_DEVICE2 (C207.1 PWRON.1 VD31.1)
RESET: 02_ATK_T527_CORE (U38.C48), 13_ATK_T527_DEVICE2 (C208.1 RESET.1 VD33.1)
U3-PCIE21-RX_N: 02_ATK_T527_CORE (U38.B44), 08_ATK_T527_USBOTG&HOST (R261.1)
U3-PCIE21-RX_P: 02_ATK_T527_CORE (U38.B45), 08_ATK_T527_USBOTG&HOST (R262.1)
U3-PCIE21-TX_N: 02_ATK_T527_CORE (U38.B47), 08_ATK_T527_USBOTG&HOST (C209.1)
U3-PCIE21-TX_P: 02_ATK_T527_CORE (U38.B48), 08_ATK_T527_USBOTG&HOST (C210.1)
USB0-D_N: 02_ATK_T527_CORE (U38.D75), 08_ATK_T527_USBOTG&HOST (USB_OTG.5 USB_OTG.7 VD12.1)
USB0-D_P: 02_ATK_T527_CORE (U38.D76), 08_ATK_T527_USBOTG&HOST (USB_OTG.6 USB_OTG.8 VD11.1)
USB1-D_N: 02_ATK_T527_CORE (U38.D78), 08_ATK_T527_USBOTG&HOST (U18.10)
USB1-D_P: 02_ATK_T527_CORE (U38.D79), 08_ATK_T527_USBOTG&HOST (U18.11)
USB2-D_N: 02_ATK_T527_CORE (U38.B41), 08_ATK_T527_USBOTG&HOST (USB3.0.2 VD34.1)
USB2-D_P: 02_ATK_T527_CORE (U38.B42), 08_ATK_T527_USBOTG&HOST (USB3.0.3 VD35.1)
